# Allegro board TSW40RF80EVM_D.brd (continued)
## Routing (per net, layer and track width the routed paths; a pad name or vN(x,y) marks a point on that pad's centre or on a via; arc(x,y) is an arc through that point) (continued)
DVDD_1P0V: length 120.4
  L8_SIG w0.102: 18.08,19.7 18.08,20.12 17.88,20.32 17.88,22.1 v1(18.25,22.47)
  L8_SIG w0.127: v1(91.47,13.44) 90.93,13.97 89.18,13.97 88.04,12.83 87.73,12.83 87.86,12.7 87.86,12.34 87.58,12.06 87.22,12.06 86.94,12.34 86.94,12.7 87.07,12.83 86.46,12.83 81.05,7.42 74.55,7.42 71.58,10.39 49.35,10.39 47.8,8.84 32.51,8.84 29.84,11.51 21.67,11.51 17.37,15.8 17.37,16.84 18.08,17.55 18.08,19.7
  BOTTOM w0.305: 20.22,22.84 19.57,23.48 ; 19.57,23.48 19.57,23.61 19.76,23.8 ; 19.57,23.48 19.44,23.48 19.23,23.27 ; 21.04,24.49 v1(20.65,24.87) ; 21.04,24.49 21.04,24.46 v1(20.65,24.07) ; 21.04,24.49 C38.1 21.13,24.31 ; v1(19.05,23.27) 18.93,23.27 18.77,23.11 18.77,23.1 18.53,22.86 18.52,22.86 18.25,22.6 v1(18.25,22.47) ; 21.13,24.31 C39.1 ; 21.13,24.31 21.13,24.13 ; v1(20.65,23.27) v1(19.85,24.07) v1(19.85,23.27) ; 21.13,24.13 21.45,23.8 v1(21.45,23.27) ; 21.13,24.13 20.65,23.65 ; C39.1 21.56,23.38 v1(21.45,23.27) ; C39.1 21.29,23.88 21.07,23.66 ; v1(21.45,23.27) 21.56,23.16 21.56,22.78 ; 21.07,23.66 21.07,23.27 21.56,22.78 ; 21.07,23.66 20.68,23.27 ; 19.62,23.03 19.85,23.26 ; 19.62,23.03 19.37,23.27 ; 19.62,23.03 19.85,22.79 ; 21.56,22.78 C41.1
  BOTTOM w0.381: v1(20.65,24.87) v1(19.85,24.87) ; v1(20.65,24.87) v1(20.65,24.07) ; v1(20.65,24.87) v1(19.85,24.07) ; v1(19.85,24.87) v1(20.65,24.07) ; v1(19.85,24.87) v1(19.85,24.07) ; v1(20.65,24.07) v1(19.85,23.27) ; v1(20.65,24.07) v1(21.45,23.27) v1(20.65,23.27) ; v1(20.65,24.07) v1(19.85,24.07) ; v1(20.65,24.07) v1(20.65,23.27) ; v1(20.65,24.07) v1(20.65,23.27) ; v1(19.85,20.07) v1(19.85,20.87) v1(19.85,21.67) v1(19.85,22.47) ; v1(20.65,23.27) v1(19.85,22.47) ; v1(20.65,23.27) v1(19.85,23.27) ; 19.76,23.8 19.76,23.37 v1(19.85,23.27) ; v1(19.85,23.27) v1(19.85,22.47) ; v1(19.85,23.27) v1(19.05,23.27)
  vias: v1(28.65,18.03) v1(28.65,16.99) v1(29.54,18.03) v1(29.54,16.99) v1(30.4,18.03) v1(30.4,16.99) v1(31.27,18.03) v1(31.27,16.99) v1(32.16,18.03) v1(32.16,16.99) v1(33.02,18) v1(33.02,16.97)
GND: length 4342
  TOP w0.127: D1.2 v1(76.4,50.5)
  TOP w0.203: v3(31.14,56.3) 30.11,56.3 v3(29.67,56.74) ; v3(21.26,57.63) 21.46,57.43 21.67,57.43 ; v3(31.14,59.3) 29.83,59.3 29.36,59.77 ; v3(27.3,58.83) 27.3,58.67 27.43,58.55 U4.2 ; v3(31.14,57.8) 29.91,57.8 29.39,57.28 ; v3(24.94,56.82) 24.69,57.07 24.69,57.12 ; v1(152.5,46.48) 148.84,46.48 148.08,47.24 ; v3(31.14,60.8) 30.11,60.8 v3(29.64,60.33) ; v3(21.11,60.12) 21.44,59.79 21.56,59.79 ; U3.2 v8(27.41,61.29) ; 24.69,58.04 24.69,58.06 v8(24.23,58.52) ; v3(40.94,63.47) 40.94,63.45 ; U29.2 v3(22.1,61.14) ; 24.66,59.66 v8(24.66,59.21)
  TOP w0.254: 135.05,18.59 J15.MT1 ; 26.92,57.84 26.64,57.84 v8(26.44,57.63) ; v3(31.67,63.68) 31.79,63.56 U2.18
  TOP w0.305: v3(40.94,60.3) 42.31,60.3 v3(42.34,60.33) 42.77,60.33 v3(43.18,60.73) 43.87,61.42 v3(44.07,61.42) 44.09,61.44 v3(45.03,61.44) ; C186.1 70.89,49.26 v5(70.83,49.2) 71.07,48.97 C191.1 ; v5(37.23,44.56) 37.06,44.6 36.38,44.6 v5(36.21,44.56) ; U21.18 65.52,11.39 v1(65.53,11.4) ; v1(101.88,49.56) 101.88,49.55 C250.1 ; v3(40.97,53.54) 41.2,53.77 42.14,53.77 v3(42.34,53.57) 43.46,53.57 v3(43.61,53.72) 43.89,53.72 v3(44.37,54.2) 44.96,54.79 v3(45.03,54.79) ; v1(15.05,20.87) v1(14.25,20.87) 14.24,20.87 v1(13.03,19.66) ; C264.2 88.15,41.99 v1(88.22,42.07) ; C236.1 34.18,44.47 v5(34.18,44.56) ; v1(14.81,17.14) 14.81,18.16 v1(15.06,18.41) ; 39.65,38.13 39.47,38.13 v5(39.26,38.08) ; v1(15.05,21.67) v1(14.25,21.67) ; C195.2 72.8,48.49 v3(72.72,48.41) ; v1(40.82,36.86) 40.26,36.86 39.45,37.67 C238.1 ; v5(33.17,39.1) 32.64,39.62 R122.1 ; v5(33.17,42.65) 32.92,42.41 C232.1 ; 114.24,10.87 U23.6 U23.5 114.89,10.94 v6(114.67,10.72) ; v3(39.62,64.85) 39.29,64.52 v3(39.29,63.6) ; v1(48.92,39.73) 48.95,39.7 D5.2 ; v3(39.09,50.57) 38.84,50.32 38.15,50.32 38.07,50.39 ; U2.37 31.79,53.43 v3(31.62,53.26) ; v5(39.26,41) 39.43,41.17 R87.2 ; v3(42.39,61.8) 42.39,62.2 v3(42.9,62.71) 43.26,63.07 v3(44.02,63.07) v3(44.91,63.07) ; v3(44.88,58.19) 44.15,57.45 v3(44.12,57.45) 43.48,56.82 v3(43.26,56.82) 43.23,56.79 v3(42.42,56.79) 42.42,56.8 v3(40.94,56.8) ; v3(42.42,55.27) v3(43.46,55.27) 43.66,55.27 v3(44.27,55.88) 44.88,56.49 v3(45.06,56.49) ; C241.2 32.87,43.41 v5(33.17,43.57) ; v3(39.98,51.92) 39.29,52.6 v3(39.29,53.65) ; v1(86.5,42.07) 86.57,41.99 C265.1 ; v5(70.83,47.17) 71.07,47.4 C188.1 71.07,47.95 v5(70.83,48.18) ; U17.9 93.38,16 U17.6 ; U21.8 v5(65.52,7.87) v5(65.52,8.57) ; v1(152.5,42.67) 152.53,42.67 v2(153.16,42.04) ; v6(93.34,16.42) 93.12,16.65 U17.5 ; v5(39.26,43.54) 39.36,43.64 C234.1 ; D3.2 49.12,35.38 v1(49.12,34.62) ; v5(38.25,38.08) 37.95,38.08 37.95,37.97 ; v3(45.03,59.79) 44.42,59.79 v3(44.04,59.41) 43.23,58.6 v3(43.18,58.6) 42.57,58.6 v3(42.39,58.78) ; v5(69.82,49.2) 70.13,49.51 C182.2
  TOP w0.381: C340.2 113.94,37.54 v1(113.94,38.25) ; v1(30.56,21.34) v1(28.91,21.34) 26.85,21.34 26.8,21.29 v1(24.38,21.29) 23.83,21.29 ; R190.1 110.44,41.15 v2(110.29,41) ; v1(22.25,22.47) U1.C2 v1(22.25,20.87) ; R189.1 111.43,41.12 v2(111.3,41) 111.43,40.87 R188.1 111.43,40.11 v2(111.3,39.98) 111.05,39.73 C348.2 111.05,39.22 v2(111.3,38.96) ; v1(22.63,31.14) 22.66,31.11 v1(25.93,31.11) 25.96,31.09 v1(28.22,31.09) v1(29.79,31.09) 30.58,31.09 ; 39.24,38.3 39.45,38.1 C238.1
  TOP w0.432: JP4.3 67.7,34.64 ; JP4.3 66.05,33 ; JP4.3 65.79,33.82 ; JP4.3 67.97,33.82 ; JP4.3 66.05,34.64 ; JP4.3 67.7,33 ; JP4.3 66.88,32.73 ; TP7.1 88.27,19 ; TP7.1 87.35,16.87 ; TP7.1 87.05,17.78 ; TP7.1 89.18,18.69 ; TP7.1 88.27,16.56 ; TP7.1 89.18,16.87 ; TP7.1 87.35,18.69 ; TP7.1 89.48,17.78 ; 119.51,44.91 TP9.1 ; TP9.1 121.33,46.73 ; TP9.1 121.33,44.91 ; TP9.1 119.51,46.73 ; TP9.1 120.42,47.04 ; TP9.1 120.42,44.6 ; J17.2 139.94,2.75 ; J17.2 137.05,2.75 ; J17.2 138.49,7.62 ; J17.2 138.49,2.75 ; J17.2 137.05,5.19 ; J17.2 139.94,7.62 ; J17.2 139.94,5.19 ; TP14.1 77.29,44.86 ; TP14.1 76.07,46.08 ; TP14.1 75.16,43.94 ; TP14.1 76.07,43.64 ; TP14.1 76.99,45.77 ; TP14.1 75.16,45.77 ; TP14.1 76.99,43.94 ; TP14.1 74.85,44.86 ; J15.5 130.84,19.08 ; J15.5 130.01,18.81 ; J15.5 130.01,17.16 ; J15.5 130.84,16.89 ; J15.5 131.66,17.16 ; J15.5 131.66,18.81 ; J38.2 113.37,32.45 ; J38.2 112.5,32.16 ; J38.2 111.33,33.32 ; J38.2 111.62,34.2 ; J38.2 111.62,32.45 ; J38.2 113.67,33.32 ; J38.2 112.5,34.49 ; J38.2 113.37,34.2 ; TP8.1 45.06,48.82 ; TP8.1 45.06,50.65 ; TP8.1 42.93,49.73 ; TP8.1 45.36,49.73 ; TP8.1 44.15,48.51 ; TP8.1 43.23,50.65 ; TP8.1 43.23,48.82 ; 80.56,9.75 JP2.3 ; JP2.3 81.38,9.49 ; JP2.3 82.21,9.75 ; JP2.3 80.29,10.58 ; JP2.3 82.47,10.58 ; JP2.3 80.56,11.4 ; JP2.3 82.21,11.4 ; 150.81,3.54 TP11.1 ; TP11.1 153.59,2.36 ; TP11.1 150.81,1.18 ; TP11.1 153.18,1.18 ; TP11.1 150.39,2.36 ; TP11.1 151.99,3.96 ; TP11.1 151.99,0.76 ; TP11.1 153.18,3.54 ; 20.27,46.38 TP6.1 ; TP6.1 21.18,46.69 ; TP6.1 19.36,48.51 ; TP6.1 19.36,46.69 ; TP6.1 21.49,47.6 ; TP6.1 21.18,48.51 ; TP6.1 19.05,47.6 ; TP6.1 20.27,48.82 ; 150.44,65.74 TP1.1 ; TP1.1 152.58,66.65 ; TP1.1 150.75,64.82 ; TP1.1 152.88,65.74 ; TP1.1 152.58,64.82 ; TP1.1 150.75,66.65 ; TP1.1 151.66,64.52 ; TP1.1 151.66,66.95 ; 13.58,42.67 HS1.MTG1 ; HS1.MTG1 16.87,45.96 ; HS1.MTG1 16.87,39.38 ; HS1.MTG1 20.16,42.67 ; HS1.MTG1 14.49,40.3 ; HS1.MTG1 19.24,40.3 ; HS1.MTG1 19.24,45.05 ; HS1.MTG1 14.49,45.05 ; 78.59,9.49 JP1.3 ; JP1.3 79.41,9.75 ; JP1.3 77.76,9.75 ; JP1.3 79.41,11.4 ; JP1.3 77.49,10.58 ; JP1.3 77.76,11.4 ; JP1.3 79.68,10.58 ; 5.61,8.89 TP2.1 ; TP2.1 7.44,8.89 ; TP2.1 7.44,10.72 ; TP2.1 6.53,11.02 ; TP2.1 5.61,10.72 ; TP2.1 6.53,8.58 ; TP2.1 5.31,9.8 ; TP2.1 7.75,9.8 ; J12.4 60.79,44.75 ; J12.4 57.9,45.97 ; J12.4 59.56,47.64 ; J12.4 58.34,47.2 ; J12.4 61.23,45.97 ; J12.4 60.79,47.2 ; J12.4 58.34,44.75 ; J12.4 59.56,44.31 ; 81.85,36.28 JP8.2 ; JP8.2 81.58,35.46 ; JP8.2 83.5,34.63 ; JP8.2 83.77,35.46 ; JP8.2 83.5,36.28 ; JP8.2 81.85,34.63 ; 52.82,51.05 J12.2 ; J12.2 54.48,49.39 ; J12.2 56.15,51.05 ; J12.2 53.26,49.83 ; J12.2 55.71,49.83 ; 18.93,6.95 HS1.MTG2 ; HS1.MTG2 23.69,2.2 ; HS1.MTG2 23.69,6.95 ; HS1.MTG2 18.02,4.57 ; HS1.MTG2 21.31,7.86 ; HS1.MTG2 21.31,1.28 ; HS1.MTG2 24.6,4.57 ; HS1.MTG2 18.93,2.2 ; 78.73,48.4 JP3.2 ; JP3.2 80.65,49.23 ; JP3.2 80.38,48.4 ; JP3.2 80.38,50.05 ; JP3.2 78.73,50.05 ; JP3.2 78.46,49.23 ; 136.08,14.26 J15.MT1 ; J15.MT1 136.08,19.11 ; J15.MT1 137.34,16.69 ; J15.MT1 134.82,16.69 ; J15.MT1 134.82,14.26 ; J15.MT1 137.34,14.26 ; 128.79,14.26 J15.MT2 ; J15.MT2 130.05,19.11 ; J15.MT2 128.79,19.11 ; J15.MT2 127.53,19.11 ; J15.MT2 130.05,16.69 ; J12.5 56.15,45.97 ; J12.5 54.48,44.31 ; J12.5 55.71,44.75 ; J12.5 52.82,45.97 ; J12.5 53.26,44.75 ; J12.5 54.48,47.64 ; J12.5 55.71,47.2 ; J12.5 53.26,47.2 ; JP7.2 81.87,43.19 ; JP7.2 79.96,42.37 ; JP7.2 82.14,42.37 ; JP7.2 80.23,43.19 ; 134.35,10.22 J17.3 ; J17.3 135.79,10.22 ; J17.3 134.35,7.79 ; J17.3 135.79,5.35 ; J17.3 137.24,7.79 ; J17.3 137.24,10.22 ; J12.3 61.23,51.05 ; J12.3 60.79,49.83 ; J12.3 59.56,52.72 ; J12.3 60.79,52.28 ; J12.3 57.9,51.05 ; J12.3 58.34,52.28 ; 66.44,41.1 JP5.1 ; JP5.1 66.44,42.19 ; JP5.1 68.62,42.19 ; JP5.1 67.53,42.19
  TOP w0.508: C235.1 34.11,44.63 v5(34.18,44.56) ; C236.1 34.36,44.56 v5(35.2,44.56) v5(36.21,44.56) v5(37.23,44.56) v5(38.25,44.56) ; C342.1 111.15,38.81 v2(111.3,38.96) ; C425.2 115.39,10.08 v6(114.67,10.08) v6(113.92,10.08) ; R343.2 113.96,38.27 v1(113.94,38.25) ; R200.2 117.2,41.1 117.42,40.87 117.42,40.49 ; U23.9 114.24,10.71 114.24,10.87 114.94,11.56 C426.1 ; C80.1 v1(27.56,12.7) ; 132.26,40.77 131.85,41.17 131.44,41.17 ; R206.2 124.36,41.22 124.79,40.79
  L2_GND w0.406: MT3.1 95.36,32.91 ; MT3.1 92.4,35.87 ; MT3.1 93.88,32.37 ; MT3.1 93.88,36.41 ; MT3.1 95.36,35.87 ; MT3.1 91.86,34.39 ; MT3.1 95.9,34.39 ; MT3.1 92.4,32.91
  L2_GND w0.432: J15.MT1 137.34,16.69 ; J15.MT1 137.34,19.11 ; J15.MT1 136.08,14.26 ; J15.MT1 134.82,16.69 ; J15.MT1 137.34,14.26 ; J15.MT1 134.82,14.26 ; J15.MT1 136.08,19.11 ; J12.4 59.56,47.64 ; J12.4 61.23,45.97 ; J12.4 60.79,44.75 ; J12.4 58.34,47.2 ; J12.4 57.9,45.97 ; J12.4 60.79,47.2 ; J12.4 59.56,44.31 ; J12.4 58.34,44.75 ; 18.93,6.95 HS1.MTG2 ; HS1.MTG2 23.69,6.95 ; HS1.MTG2 23.69,2.2 ; HS1.MTG2 18.02,4.57 ; HS1.MTG2 18.93,2.2 ; HS1.MTG2 21.31,7.86 ; HS1.MTG2 24.6,4.57 ; HS1.MTG2 21.31,1.28 ; 111.62,32.45 J38.2 ; J38.2 112.5,34.49 ; J38.2 113.67,33.32 ; J38.2 113.37,32.45 ; J38.2 113.37,34.2 ; J38.2 112.5,32.16 ; J38.2 111.33,33.32 ; J38.2 111.62,34.2 ; 81.85,34.63 JP8.2 ; JP8.2 83.5,34.63 ; JP8.2 81.58,35.46 ; JP8.2 83.77,35.46 ; JP8.2 83.5,36.28 ; JP8.2 81.85,36.28 ; TP9.1 121.33,44.91 ; TP9.1 119.51,46.73 ; TP9.1 119.2,45.82 ; TP9.1 120.42,44.6 ; TP9.1 119.51,44.91 ; TP9.1 120.42,47.04 ; TP9.1 121.64,45.82 ; TP9.1 121.33,46.73 ; 67.53,40 JP5.1 ; JP5.1 66.71,41.92 ; JP5.1 66.71,40.27 ; JP5.1 67.53,42.19 ; JP5.1 68.35,41.92 ; JP5.1 68.35,40.27 ; JP5.1 66.44,41.1 ; JP3.2 80.38,50.05 ; JP3.2 80.38,48.4 ; JP3.2 78.73,50.05 ; JP3.2 80.65,49.23 ; JP3.2 78.73,48.4 ; JP3.2 78.46,49.23 ; J15.5 131.66,17.16 ; J15.5 130.01,18.81 ; J15.5 130.01,17.16 ; J15.5 130.84,19.08 ; J15.5 131.66,18.81 ; J15.5 130.84,16.89 ; 77.76,9.75 JP1.3 ; JP1.3 79.68,10.58 ; JP1.3 77.49,10.58 ; JP1.3 79.41,9.75 ; JP1.3 77.76,11.4 ; JP1.3 79.41,11.4 ; JP1.3 78.59,9.49 ; 7.72,63.51 MT2.1 ; MT2.1 5.7,65.53 ; MT2.1 9.74,65.53 ; MT2.1 6.24,67.01 ; MT2.1 6.24,64.05 ; MT2.1 9.2,67.01 ; MT2.1 9.2,64.05 ; MT2.1 7.72,67.55 ; 5.31,9.8 TP2.1 ; TP2.1 6.53,8.58 ; TP2.1 5.61,8.89 ; TP2.1 7.44,10.72 ; TP2.1 7.44,8.89 ; TP2.1 6.53,11.02 ; TP2.1 5.61,10.72 ; TP2.1 7.75,9.8 ; J12.2 56.15,51.05 ; J12.2 55.71,49.83 ; J12.2 53.26,52.28 ; J12.2 52.82,51.05 ; J12.2 54.48,49.39 ; J12.2 54.48,52.72 ; J12.2 53.26,49.83 ; J12.2 55.71,52.28 ; J17.3 137.24,7.79 ; J17.3 135.79,5.35 ; J17.3 134.35,7.79 ; J17.3 137.24,10.22 ; J17.3 135.79,10.22 ; J17.3 134.35,5.35 ; J17.3 134.35,10.22 ; 7.98,12.71 MT1.1 ; MT1.1 9.45,16.21 ; MT1.1 6.5,16.21 ; MT1.1 10,14.73 ; MT1.1 7.98,16.75 ; MT1.1 6.5,13.25 ; MT1.1 9.45,13.25 ; MT1.1 5.96,14.73 ; TP1.1 152.88,65.74 ; TP1.1 150.75,64.82 ; TP1.1 150.44,65.74 ; TP1.1 152.58,66.65 ; TP1.1 150.75,66.65 ; TP1.1 151.66,64.52 ; TP1.1 152.58,64.82 ; TP1.1 151.66,66.95 ; JP4.3 67.97,33.82 ; JP4.3 66.05,34.64 ; JP4.3 66.05,33 ; JP4.3 66.88,32.73 ; JP4.3 65.79,33.82 ; JP4.3 67.7,34.64 ; JP4.3 67.7,33 ; TP14.1 76.07,46.08 ; TP14.1 75.16,43.94 ; TP14.1 74.85,44.86 ; TP14.1 77.29,44.86 ; TP14.1 76.99,43.94 ; TP14.1 75.16,45.77 ; TP14.1 76.07,43.64 ; TP14.1 76.99,45.77 ; 43.23,48.82 TP8.1 ; TP8.1 45.06,50.65 ; TP8.1 42.93,49.73 ; TP8.1 45.36,49.73 ; TP8.1 43.23,50.65 ; TP8.1 44.15,48.51 ; TP8.1 45.06,48.82 ; TP8.1 44.15,50.95 ; J12.3 60.79,52.28 ; J12.3 59.56,52.72 ; J12.3 60.79,49.83 ; J12.3 57.9,51.05 ; J12.3 61.23,51.05 ; J12.3 58.34,52.28 ; J12.3 58.34,49.83 ; J15.MT2 130.05,19.11 ; J15.MT2 130.05,16.69 ; J15.MT2 127.53,14.26 ; J15.MT2 128.79,14.26 ; J15.MT2 128.79,19.11 ; J15.MT2 127.53,16.69 ; J15.MT2 127.53,19.11 ; 80.29,10.58 JP2.3 ; JP2.3 80.56,9.75 ; JP2.3 82.21,11.4 ; JP2.3 82.21,9.75 ; JP2.3 82.47,10.58 ; JP2.3 81.38,9.49 ; JP2.3 80.56,11.4 ; TP6.1 21.18,46.69 ; TP6.1 19.36,48.51 ; TP6.1 19.36,46.69 ; TP6.1 20.27,46.38 ; TP6.1 21.49,47.6 ; TP6.1 20.27,48.82 ; TP6.1 19.05,47.6 ; TP6.1 21.18,48.51 ; JP7.2 82.14,42.37 ; JP7.2 81.87,43.19 ; JP7.2 79.96,42.37 ; JP7.2 80.23,41.54 ; JP7.2 80.23,43.19 ; JP7.2 81.87,41.54 ; 14.49,45.05 HS1.MTG1 ; HS1.MTG1 19.24,45.05 ; HS1.MTG1 20.16,42.67 ; HS1.MTG1 16.87,45.96 ; HS1.MTG1 19.24,40.3 ; HS1.MTG1 16.87,39.38 ; HS1.MTG1 13.58,42.67 ; HS1.MTG1 14.49,40.3 ; J17.2 139.94,5.19 ; J17.2 137.05,5.19 ; J17.2 139.94,7.62 ; J17.2 138.49,2.75 ; J17.2 137.05,2.75 ; J17.2 138.49,7.62 ; J17.2 139.94,2.75 ; 88.27,16.56 TP7.1 ; TP7.1 87.35,16.87 ; TP7.1 89.18,16.87 ; TP7.1 87.35,18.69 ; TP7.1 87.05,17.78 ; TP7.1 88.27,19 ; TP7.1 89.48,17.78 ; TP7.1 89.18,18.69 ; 150.81,1.18 TP11.1 ; TP11.1 151.99,0.76 ; TP11.1 153.18,3.54 ; TP11.1 153.59,2.36 ; TP11.1 153.18,1.18 ; TP11.1 150.39,2.36 ; TP11.1 150.81,3.54 ; TP11.1 151.99,3.96 ; 53.26,47.2 J12.5 ; J12.5 54.48,47.64 ; J12.5 54.48,44.31 ; J12.5 55.71,44.75 ; J12.5 52.82,45.97 ; J12.5 56.15,45.97 ; J12.5 53.26,44.75 ; J12.5 55.71,47.2
  L3_PWR_SIG w0.432: 6.5,16.21 MT1.1 ; MT1.1 6.5,13.25 ; MT1.1 7.98,16.75 ; MT1.1 9.45,13.25 ; MT1.1 5.96,14.73 ; MT1.1 7.98,12.71 ; TP6.1 20.27,48.82 ; TP6.1 20.27,46.38 ; TP6.1 21.49,47.6 ; TP6.1 21.18,48.51 ; TP6.1 21.18,46.69 ; TP6.1 19.36,48.51 ; TP6.1 19.36,46.69 ; TP6.1 19.05,47.6 ; 79.09,48.16 JP3.2 ; JP3.2 78.73,50.05 ; JP3.2 78.46,49.23 ; JP3.2 78.73,48.4 ; J15.MT1 136.08,19.11 ; J15.MT1 136.08,14.26 ; J15.MT1 137.34,14.26 ; J15.MT1 134.82,14.26 ; J15.MT1 134.82,16.69 ; J15.MT1 137.34,19.11 ; J15.MT1 137.34,16.69 ; HS1.MTG1 19.24,45.05 ; HS1.MTG1 14.49,45.05 ; HS1.MTG1 13.58,42.67 ; HS1.MTG1 20.16,42.67 ; HS1.MTG1 16.87,45.96 ; HS1.MTG1 19.24,40.3 ; HS1.MTG1 16.87,39.38 ; HS1.MTG1 14.49,40.3 ; TP9.1 120.42,47.04 ; TP9.1 121.33,46.73 ; TP9.1 121.33,44.91 ; TP9.1 121.64,45.82 ; TP9.1 119.51,46.73 ; TP9.1 119.2,45.82 ; 18.02,4.57 HS1.MTG2 ; HS1.MTG2 23.69,2.2 ; HS1.MTG2 24.6,4.57 ; HS1.MTG2 21.31,1.28 ; HS1.MTG2 18.93,6.95 ; HS1.MTG2 18.93,2.2 ; HS1.MTG2 23.69,6.95 ; 58.34,44.75 J12.4 ; J12.4 57.9,45.97 ; J12.4 60.79,44.75 ; J12.4 59.56,44.31 ; J12.4 60.79,47.2 ; J12.4 59.56,47.64 ; J12.4 58.34,47.2 ; J12.4 61.23,45.97 ; TP7.1 89.18,18.69 ; TP7.1 88.27,16.56 ; TP7.1 88.27,19 ; TP7.1 87.35,18.69 ; TP7.1 87.35,16.87 ; TP7.1 89.48,17.78 ; TP7.1 89.18,16.87 ; TP7.1 87.05,17.78 ; 66.05,33 JP4.3 ; JP4.3 67.7,34.64 ; JP4.3 66.88,32.73 ; JP4.3 67.97,33.82 ; JP4.3 67.7,33 ; JP4.3 66.05,34.64 ; JP4.3 65.79,33.82 ; J17.2 139.94,5.19 ; J17.2 138.49,7.62 ; J17.2 139.94,7.62 ; J17.2 137.05,5.19 ; J17.2 139.94,2.75 ; J17.2 138.49,2.75 ; J17.2 137.05,2.75 ; 43.23,50.65 TP8.1 ; TP8.1 43.23,48.82 ; TP8.1 44.15,48.51 ; TP8.1 42.93,49.73 ; TP8.1 45.36,49.73 ; TP8.1 45.06,50.65 ; TP8.1 44.15,50.95 ; TP8.1 45.06,48.82 ; 127.53,16.69 J15.MT2 ; J15.MT2 128.79,14.26 ; J15.MT2 130.05,16.69 ; J15.MT2 127.53,14.26 ; MT2.1 9.2,64.05 ; MT2.1 7.72,63.51 ; MT2.1 9.74,65.53 ; MT2.1 6.24,67.01 ; MT2.1 9.2,67.01 ; MT2.1 7.72,67.55 ; MT2.1 6.24,64.05 ; MT2.1 5.7,65.53 ; TP14.1 76.99,45.77 ; TP14.1 75.16,43.94 ; TP14.1 75.16,45.77 ; TP14.1 76.07,46.08 ; TP14.1 74.85,44.86 ; TP14.1 77.29,44.86 ; TP14.1 76.07,43.64 ; TP14.1 76.99,43.94 ; 77.76,11.4 JP1.3 ; JP1.3 77.49,10.58 ; JP1.3 79.41,11.4 ; JP1.3 79.68,10.58 ; TP11.1 153.59,2.36 ; TP11.1 151.99,0.76 ; TP11.1 150.81,3.54 ; TP11.1 150.39,2.36 ; TP11.1 150.81,1.18 ; TP11.1 153.18,3.54 ; TP11.1 151.99,3.96 ; TP11.1 153.18,1.18 ; 53.26,47.2 J12.5 ; J12.5 54.48,44.31 ; J12.5 55.71,44.75 ; J12.5 56.15,45.97 ; J12.5 52.82,45.97 ; J12.5 55.71,47.2 ; J12.5 54.48,47.64 ; J12.5 53.26,44.75 ; 150.44,65.74 TP1.1 ; TP1.1 150.75,66.65 ; TP1.1 150.75,64.82 ; TP1.1 152.58,66.65 ; TP1.1 152.88,65.74 ; TP1.1 151.66,64.52 ; TP1.1 152.58,64.82 ; TP1.1 151.66,66.95 ; JP2.3 82.21,11.4 ; JP2.3 82.47,10.58 ; JP2.3 80.56,11.4 ; JP2.3 80.29,10.58 ; J12.3 59.56,52.72 ; J12.3 58.34,49.83 ; J12.3 58.34,52.28 ; J12.3 60.79,52.28 ; J12.3 61.23,51.05 ; J12.3 57.9,51.05 ; J12.3 60.79,49.83 ; J12.2 55.71,52.28 ; J12.2 56.15,51.05 ; J12.2 54.48,49.39 ; J12.2 52.82,51.05 ; J12.2 53.26,52.28 ; J12.2 55.71,49.83 ; J12.2 53.26,49.83 ; J12.2 54.48,52.72 ; 5.31,9.8 TP2.1 ; TP2.1 5.61,8.89 ; TP2.1 7.44,10.72 ; TP2.1 6.53,11.02 ; TP2.1 7.75,9.8 ; TP2.1 6.53,8.58 ; TP2.1 7.44,8.89 ; TP2.1 5.61,10.72 ; 135.79,5.35 J17.3 ; J17.3 135.79,10.22 ; J17.3 137.24,10.22 ; J17.3 134.35,5.35 ; J17.3 134.35,7.79 ; J17.3 137.24,7.79 ; J17.3 134.35,10.22 ; 130.38,16.91 J15.5 ; J15.5 130.01,17.16 ; J15.5 131.66,17.16 ; J15.5 130.84,16.89 ; JP5.1 67.53,42.19 ; JP5.1 66.71,41.92 ; JP5.1 66.71,40.27 ; JP5.1 66.44,41.1 ; JP5.1 68.35,41.92 ; JP5.1 68.35,40.27 ; JP5.1 67.53,40 ; 81.85,34.63 JP8.2 ; JP8.2 82.22,34.39 ; JP8.2 81.58,35.46 ; JP8.2 81.61,35
  L4_SIG w0.406: 91.86,34.39 MT3.1 ; MT3.1 93.88,36.41 ; MT3.1 95.36,32.91 ; MT3.1 92.4,32.91 ; MT3.1 93.88,32.37 ; MT3.1 95.36,35.87 ; MT3.1 95.9,34.39 ; MT3.1 92.4,35.87
  L4_SIG w0.432: 14.49,45.05 HS1.MTG1 ; HS1.MTG1 20.16,42.67 ; HS1.MTG1 19.24,40.3 ; HS1.MTG1 16.87,39.38 ; HS1.MTG1 19.24,45.05 ; HS1.MTG1 14.49,40.3 ; HS1.MTG1 13.58,42.67 ; HS1.MTG1 16.87,45.96 ; 58.34,52.28 J12.3 ; J12.3 60.79,52.28 ; J12.3 59.56,52.72 ; J12.3 57.9,51.05 ; J12.3 61.23,51.05 ; J12.3 60.79,49.83 ; J12.3 58.34,49.83 ; 135.79,5.35 J17.3 ; J17.3 137.24,10.22 ; J17.3 135.79,10.22 ; J17.3 137.24,7.79 ; J17.3 134.35,10.22 ; J17.3 134.35,5.35 ; J17.3 134.35,7.79 ; JP8.2 83.5,34.63 ; JP8.2 83.5,36.28 ; JP8.2 81.58,35.46 ; JP8.2 81.85,34.63 ; JP8.2 81.85,36.28 ; JP8.2 83.77,35.46 ; JP2.3 82.21,9.75 ; JP2.3 82.47,10.58 ; JP2.3 80.56,9.75 ; JP2.3 82.21,11.4 ; JP2.3 81.38,9.49 ; JP2.3 80.56,11.4 ; JP2.3 80.29,10.58 ; JP3.2 80.65,49.23 ; JP3.2 80.38,50.05 ; JP3.2 78.73,50.05 ; JP3.2 78.73,48.4 ; JP3.2 78.46,49.23 ; JP3.2 80.38,48.4 ; 150.75,64.82 TP1.1 ; TP1.1 152.58,66.65 ; TP1.1 150.75,66.65 ; TP1.1 150.44,65.74 ; TP1.1 151.66,66.95 ; TP1.1 152.88,65.74 ; TP1.1 152.58,64.82 ; TP1.1 151.66,64.52 ; J12.4 61.23,45.97 ; J12.4 60.79,44.75 ; J12.4 60.79,47.2 ; J12.4 59.56,47.64 ; J12.4 58.34,44.75 ; J12.4 59.56,44.31 ; J12.4 58.34,47.2 ; J12.4 57.9,45.97 ; TP11.1 153.18,3.54 ; TP11.1 150.81,1.18 ; TP11.1 153.18,1.18 ; TP11.1 151.99,0.76 ; TP11.1 153.59,2.36 ; TP11.1 151.99,3.96 ; TP11.1 150.39,2.36 ; TP11.1 150.81,3.54 ; TP7.1 89.48,17.78 ; TP7.1 89.18,18.69 ; TP7.1 87.35,18.69 ; TP7.1 89.18,16.87 ; TP7.1 88.27,16.56 ; TP7.1 87.05,17.78 ; TP7.1 87.35,16.87 ; TP7.1 88.27,19 ; 79.96,42.37 JP7.2 ; JP7.2 80.23,43.19 ; JP7.2 81.87,43.19 ; JP7.2 81.87,41.54 ; JP7.2 82.14,42.37 ; JP7.2 80.23,41.54 ; 19.05,47.6 TP6.1 ; TP6.1 20.27,48.82 ; TP6.1 19.36,46.69 ; TP6.1 20.27,46.38 ; TP6.1 21.49,47.6 ; TP6.1 19.36,48.51 ; TP6.1 21.18,46.69 ; TP6.1 21.18,48.51 ; 6.24,67.01 MT2.1 ; MT2.1 9.2,64.05 ; MT2.1 9.74,65.53 ; MT2.1 7.72,63.51 ; MT2.1 9.2,67.01 ; MT2.1 7.72,67.55 ; MT2.1 6.24,64.05 ; MT2.1 5.7,65.53 ; 77.49,10.58 JP1.3 ; JP1.3 79.41,11.4 ; JP1.3 79.68,10.58 ; JP1.3 78.59,9.49 ; JP1.3 79.41,9.75 ; JP1.3 77.76,11.4 ; JP1.3 77.76,9.75 ; 134.82,16.69 J15.MT1 ; J15.MT1 137.34,16.69 ; J15.MT1 137.34,14.26 ; J15.MT1 137.34,19.11 ; J15.MT1 134.82,14.26 ; J15.MT1 136.08,19.11 ; J15.MT1 136.08,14.26 ; J12.2 55.71,49.83 ; J12.2 53.26,52.28 ; J12.2 55.71,52.28 ; J12.2 52.82,51.05 ; J12.2 53.26,49.83 ; J12.2 54.48,49.39 ; J12.2 54.48,52.72 ; J12.2 56.15,51.05 ; MT1.1 10,14.73 ; MT1.1 7.98,12.71 ; MT1.1 6.5,16.21 ; MT1.1 5.96,14.73 ; MT1.1 9.45,13.25 ; MT1.1 7.98,16.75 ; MT1.1 6.5,13.25 ; MT1.1 9.45,16.21 ; 54.48,44.31 J12.5 ; J12.5 53.26,44.75 ; J12.5 54.48,47.64 ; J12.5 55.71,44.75 ; J12.5 56.15,45.97 ; J12.5 52.82,45.97 ; J12.5 55.71,47.2 ; J12.5 53.26,47.2 ; TP9.1 120.42,47.04 ; TP9.1 121.33,44.91 ; TP9.1 119.51,44.91 ; TP9.1 121.64,45.82 ; TP9.1 121.33,46.73 ; TP9.1 119.51,46.73 ; TP9.1 119.2,45.82 ; TP9.1 120.42,44.6 ; TP14.1 76.07,46.08 ; TP14.1 75.16,45.77 ; TP14.1 76.58,46.04 ; TP14.1 74.85,44.86 ; J15.MT2 128.79,19.11 ; J15.MT2 130.05,19.11 ; J15.MT2 130.05,16.69 ; J15.MT2 127.53,16.69 ; J15.MT2 128.79,14.26 ; J15.MT2 127.53,19.11 ; J15.MT2 127.53,14.26 ; JP5.1 68.35,40.27 ; JP5.1 66.44,41.1 ; JP5.1 66.71,41.92 ; JP5.1 67.53,40 ; JP5.1 66.71,40.27 ; JP4.3 67.7,34.64 ; JP4.3 66.88,32.73 ; JP4.3 67.97,33.82 ; JP4.3 65.79,33.82 ; JP4.3 66.05,34.64 ; JP4.3 66.05,33 ; JP4.3 67.7,33 ; TP8.1 45.06,50.65 ; TP8.1 43.23,50.65 ; TP8.1 42.93,49.73 ; TP8.1 44.15,50.95 ; TP8.1 45.06,48.82 ; TP8.1 43.23,48.82 ; TP8.1 44.15,48.51 ; 5.61,10.72 TP2.1 ; TP2.1 7.44,8.89 ; TP2.1 6.53,8.58 ; TP2.1 7.44,10.72 ; TP2.1 6.53,11.02 ; TP2.1 5.31,9.8 ; TP2.1 5.61,8.89 ; TP2.1 7.75,9.8 ; 111.33,33.32 J38.2 ; J38.2 112.5,32.16 ; J38.2 111.62,32.45 ; J38.2 111.62,34.2 ; J38.2 113.37,34.2 ; J38.2 113.67,33.32 ; J38.2 113.37,32.45 ; 138.49,2.75 J17.2 ; J17.2 139.94,7.62 ; J17.2 139.94,5.19 ; J17.2 138.49,7.62 ; J17.2 137.05,2.75 ; J17.2 137.05,5.19 ; J17.2 139.94,2.75 ; HS1.MTG2 23.69,2.2 ; HS1.MTG2 18.02,4.57 ; HS1.MTG2 21.31,1.28 ; HS1.MTG2 24.6,4.57 ; HS1.MTG2 18.93,6.95 ; HS1.MTG2 23.69,6.95 ; HS1.MTG2 18.93,2.2 ; HS1.MTG2 21.31,7.86 ; 130.84,16.89 J15.5 ; J15.5 130.01,18.81 ; J15.5 130.84,19.08 ; J15.5 131.66,17.16 ; J15.5 131.66,18.81 ; J15.5 130.01,17.16
  L5_GND w0.406: 92.4,32.91 MT3.1 ; MT3.1 95.36,35.87 ; MT3.1 95.36,32.91 ; MT3.1 92.4,35.87 ; MT3.1 93.88,36.41 ; MT3.1 91.86,34.39 ; MT3.1 95.9,34.39 ; MT3.1 93.88,32.37
  L5_GND w0.432: 52.82,51.05 J12.2 ; J12.2 54.48,49.39 ; J12.2 53.26,49.83 ; J12.2 56.15,51.05 ; J12.2 54.48,52.72 ; J12.2 53.26,52.28 ; J12.2 55.71,49.83 ; J12.2 55.71,52.28 ; 80.23,41.54 JP7.2 ; JP7.2 82.14,42.37 ; JP7.2 80.23,43.19 ; JP7.2 81.87,43.19 ; JP7.2 81.87,41.54 ; JP7.2 79.96,42.37 ; TP14.1 77.29,44.86 ; TP14.1 76.07,46.08 ; TP14.1 74.85,44.86 ; TP14.1 75.16,43.94 ; TP14.1 76.99,43.94 ; TP14.1 76.07,43.64 ; TP14.1 75.16,45.77 ; TP14.1 76.99,45.77 ; 88.27,16.56 TP7.1 ; TP7.1 87.35,18.69 ; TP7.1 89.48,17.78 ; TP7.1 87.35,16.87 ; TP7.1 88.27,19 ; TP7.1 89.18,16.87 ; TP7.1 89.18,18.69 ; TP7.1 87.05,17.78 ; 43.23,48.82 TP8.1 ; TP8.1 43.23,50.65 ; TP8.1 42.93,49.73 ; TP8.1 44.15,48.51 ; TP8.1 45.36,49.73 ; TP8.1 44.15,50.95 ; TP8.1 45.06,48.82 ; TP8.1 45.06,50.65 ; JP5.1 67.53,42.19 ; JP5.1 68.35,40.27 ; JP5.1 66.71,41.92 ; JP5.1 67.53,40 ; JP5.1 66.44,41.1 ; JP5.1 66.71,40.27 ; JP5.1 68.35,41.92 ; 136.08,14.26 J15.MT1 ; J15.MT1 136.08,19.11 ; J15.MT1 137.34,14.26 ; J15.MT1 134.82,14.26 ; J15.MT1 137.34,16.69 ; J15.MT1 134.82,16.69 ; J15.MT1 137.34,19.11 ; 18.93,6.95 HS1.MTG2 ; HS1.MTG2 24.6,4.57 ; HS1.MTG2 18.93,2.2 ; HS1.MTG2 23.69,6.95 ; HS1.MTG2 21.31,1.28 ; HS1.MTG2 18.02,4.57 ; HS1.MTG2 21.31,7.86 ; HS1.MTG2 23.69,2.2 ; 130.01,17.16 J15.5 ; J15.5 130.84,16.89 ; J15.5 130.84,19.08 ; J15.5 131.66,17.16 ; J15.5 131.66,18.81 ; J15.5 130.01,18.81 ; TP11.1 153.18,3.54 ; TP11.1 150.39,2.36 ; TP11.1 151.99,3.96 ; TP11.1 151.99,0.76 ; TP11.1 153.18,1.18 ; TP11.1 150.81,3.54 ; TP11.1 150.81,1.18 ; TP11.1 153.59,2.36 ; TP9.1 120.42,47.04 ; TP9.1 121.64,45.82 ; TP9.1 121.33,46.73 ; TP9.1 119.51,44.91 ; TP9.1 119.2,45.82 ; TP9.1 119.51,46.73 ; TP9.1 120.42,44.6 ; TP9.1 121.33,44.91 ; J12.5 55.71,44.75 ; J12.5 56.15,45.97 ; J12.5 53.26,47.2 ; J12.5 52.82,45.97 ; J12.5 55.71,47.2 ; J12.5 54.48,44.31 ; J12.5 54.48,47.64 ; J12.5 53.26,44.75 ; J12.3 60.79,52.28 ; J12.3 59.56,52.72 ; J12.3 58.34,49.83 ; J12.3 60.79,49.83 ; J12.3 57.9,51.05 ; J12.3 58.34,52.28 ; J12.3 61.23,51.05 ; JP2.3 82.21,9.75 ; JP2.3 80.29,10.58 ; JP2.3 82.21,11.4 ; JP2.3 80.56,9.75 ; JP2.3 82.47,10.58 ; JP2.3 80.56,11.4 ; JP2.3 81.38,9.49 ; 19.05,47.6 TP6.1 ; TP6.1 20.27,46.38 ; TP6.1 19.36,48.51 ; TP6.1 21.18,48.51 ; TP6.1 20.27,48.82 ; TP6.1 21.18,46.69 ; TP6.1 21.49,47.6 ; TP6.1 19.36,46.69 ; MT1.1 10,14.73 ; MT1.1 6.5,16.21 ; MT1.1 5.96,14.73 ; MT1.1 7.98,16.75 ; MT1.1 9.45,13.25 ; MT1.1 9.45,16.21 ; MT1.1 7.98,12.71 ; MT1.1 6.5,13.25 ; 137.05,5.19 J17.2 ; J17.2 138.49,7.62 ; J17.2 139.94,2.75 ; J17.2 138.49,2.75 ; J17.2 139.94,5.19 ; J17.2 137.05,2.75 ; J17.2 139.94,7.62 ; 66.88,32.73 JP4.3 ; JP4.3 67.97,33.82 ; JP4.3 65.79,33.82 ; JP4.3 67.7,34.64 ; JP4.3 66.05,33 ; JP4.3 67.7,33 ; JP4.3 66.05,34.64 ; 6.24,67.01 MT2.1 ; MT2.1 7.72,63.51 ; MT2.1 7.72,67.55 ; MT2.1 9.2,67.01 ; MT2.1 6.24,64.05 ; MT2.1 9.74,65.53 ; MT2.1 5.7,65.53 ; MT2.1 9.2,64.05 ; 5.61,10.72 TP2.1 ; TP2.1 7.44,10.72 ; TP2.1 7.44,8.89 ; TP2.1 6.53,8.58 ; TP2.1 6.53,11.02 ; TP2.1 5.31,9.8 ; TP2.1 5.61,8.89 ; TP2.1 7.75,9.8 ; 127.53,19.11 J15.MT2 ; J15.MT2 130.05,19.11 ; J15.MT2 128.79,19.11 ; J15.MT2 130.05,16.69 ; J15.MT2 128.79,14.26 ; J15.MT2 127.53,14.26 ; J15.MT2 127.53,16.69 ; 150.75,66.65 TP1.1 ; TP1.1 151.66,64.52 ; TP1.1 152.88,65.74 ; TP1.1 150.44,65.74 ; TP1.1 150.75,64.82 ; TP1.1 152.58,66.65 ; TP1.1 151.66,66.95 ; TP1.1 152.58,64.82 ; J38.2 113.67,33.32 ; J38.2 112.5,32.16 ; J38.2 111.62,32.45 ; J38.2 112.5,34.49 ; J38.2 113.37,34.2 ; J38.2 113.37,32.45 ; J38.2 111.33,33.32 ; J38.2 111.62,34.2 ; 81.85,34.63 JP8.2 ; JP8.2 81.58,35.46 ; JP8.2 83.5,36.28 ; JP8.2 83.77,35.46 ; JP8.2 81.85,36.28 ; JP8.2 83.5,34.63 ; HS1.MTG1 19.24,40.3 ; HS1.MTG1 14.49,40.3 ; HS1.MTG1 16.87,39.38 ; HS1.MTG1 13.58,42.67 ; HS1.MTG1 20.16,42.67 ; HS1.MTG1 19.24,45.05 ; HS1.MTG1 16.87,45.96 ; HS1.MTG1 14.49,45.05 ; 78.59,9.49 JP1.3 ; JP1.3 79.68,10.58 ; JP1.3 77.76,9.75 ; JP1.3 77.76,11.4 ; JP1.3 79.41,11.4 ; JP1.3 79.41,9.75 ; JP1.3 77.49,10.58 ; JP3.2 80.65,49.23 ; JP3.2 80.38,48.4 ; JP3.2 78.73,48.4 ; JP3.2 78.73,50.05 ; JP3.2 80.38,50.05 ; JP3.2 78.46,49.23 ; J12.4 60.79,47.2 ; J12.4 59.56,44.31 ; J12.4 60.79,44.75 ; J12.4 59.56,47.64 ; J12.4 61.23,45.97 ; J12.4 58.34,47.2 ; J12.4 57.9,45.97 ; J12.4 58.34,44.75 ; 134.35,5.35 J17.3 ; J17.3 137.24,10.22 ; J17.3 134.35,7.79 ; J17.3 137.24,7.79 ; J17.3 135.79,5.35 ; J17.3 134.35,10.22 ; J17.3 135.79,10.22
  L6_SIG w0.406: MT3.1 95.9,34.39 ; MT3.1 95.36,32.91 ; MT3.1 93.88,32.37 ; MT3.1 93.88,36.41 ; MT3.1 92.4,32.91 ; MT3.1 95.36,35.87 ; MT3.1 91.86,34.39
  L6_SIG w0.432: J12.4 60.79,47.2 ; J12.4 58.34,44.75 ; J12.4 57.9,45.97 ; J12.4 60.79,44.75 ; J12.4 61.23,45.97 ; 130.01,17.16 J15.5 ; J15.5 131.66,18.81 ; J15.5 130.01,18.81 ; J15.5 131.66,17.16 ; J15.5 130.84,16.89 ; J15.5 130.84,19.08 ; 14.49,45.05 HS1.MTG1 ; HS1.MTG1 19.24,45.05 ; HS1.MTG1 20.16,42.67 ; HS1.MTG1 16.87,39.38 ; HS1.MTG1 16.87,45.96 ; HS1.MTG1 13.58,42.67 ; HS1.MTG1 14.49,40.3 ; HS1.MTG1 19.24,40.3 ; JP3.2 80.38,48.4 ; JP3.2 78.73,48.4 ; JP3.2 78.46,49.23 ; JP3.2 80.38,50.05 ; JP3.2 78.73,50.05 ; JP3.2 80.65,49.23 ; 5.61,8.89 TP2.1 ; TP2.1 7.75,9.8 ; TP2.1 6.53,11.02 ; TP2.1 7.44,10.72 ; TP2.1 5.61,10.72 ; TP2.1 5.31,9.8 ; TP2.1 6.53,8.58 ; TP2.1 7.44,8.89 ; 150.75,66.65 TP1.1 ; TP1.1 151.66,66.95 ; TP1.1 152.58,64.82 ; TP1.1 152.58,66.65 ; TP1.1 150.75,64.82 ; TP1.1 152.88,65.74 ; TP1.1 150.44,65.74 ; TP1.1 151.66,64.52 ; J17.2 139.94,2.75 ; J17.2 139.94,7.62 ; J17.2 138.49,2.75 ; J17.2 138.49,7.62 ; J17.2 139.94,5.19 ; J17.2 137.05,5.19 ; J17.2 137.05,2.75 ; J15.MT1 137.34,19.11 ; J15.MT1 137.34,16.69 ; J15.MT1 134.82,14.26 ; J15.MT1 137.34,14.26 ; J15.MT1 136.08,14.26 ; J15.MT1 134.82,16.69 ; J15.MT1 136.08,19.11 ; J38.2 112.5,34.49 ; J38.2 113.67,33.32 ; J38.2 111.33,33.32 ; J38.2 112.5,32.16 ; J38.2 113.37,32.45 ; J38.2 113.37,34.2 ; J38.2 111.62,32.45 ; J38.2 111.62,34.2 ; 127.53,16.69 J15.MT2 ; J15.MT2 127.53,14.26 ; J15.MT2 127.53,19.11 ; J15.MT2 130.05,19.11 ; J15.MT2 128.79,19.11 ; J15.MT2 130.05,16.69 ; J15.MT2 128.79,14.26 ; 87.05,17.78 TP7.1 ; TP7.1 89.18,16.87 ; TP7.1 88.27,16.56 ; TP7.1 88.27,19 ; TP7.1 87.35,18.69 ; TP7.1 87.35,16.87 ; TP7.1 89.18,18.69 ; TP7.1 89.48,17.78 ; TP14.1 76.07,46.08 ; TP14.1 74.85,44.86 ; TP14.1 75.16,43.94 ; TP14.1 76.99,45.77 ; TP14.1 75.16,45.77 ; 18.93,6.95 HS1.MTG2 ; HS1.MTG2 24.6,4.57 ; HS1.MTG2 18.93,2.2 ; HS1.MTG2 21.31,1.28 ; HS1.MTG2 18.02,4.57 ; HS1.MTG2 23.69,6.95 ; HS1.MTG2 21.31,7.86 ; HS1.MTG2 23.69,2.2 ; 134.35,10.22 J17.3 ; J17.3 135.79,10.22 ; J17.3 137.24,10.22 ; J17.3 134.35,5.35 ; J17.3 137.24,7.79 ; J17.3 134.35,7.79 ; J17.3 135.79,5.35 ; MT2.1 9.2,67.01 ; MT2.1 9.2,64.05 ; MT2.1 7.72,63.51 ; MT2.1 9.74,65.53 ; MT2.1 6.24,67.01 ; MT2.1 7.72,67.55 ; MT2.1 5.7,65.53 ; MT2.1 6.24,64.05 ; 44.15,48.51 TP8.1 ; TP8.1 45.36,49.73 ; TP8.1 45.06,50.65 ; TP8.1 42.93,49.73 ; TP8.1 45.06,48.82 ; TP8.1 43.23,48.82 ; 150.81,1.18 TP11.1 ; TP11.1 150.39,2.36 ; TP11.1 151.99,3.96 ; TP11.1 153.59,2.36 ; TP11.1 151.99,0.76 ; TP11.1 153.18,1.18 ; TP11.1 150.81,3.54 ; TP11.1 153.18,3.54 ; J12.2 55.71,49.83 ; J12.2 56.15,51.05 ; J12.2 53.26,49.83 ; J12.2 54.48,49.39 ; J12.2 52.82,51.05 ; J12.5 55.71,44.75 ; J12.5 53.26,47.2 ; J12.5 54.48,47.64 ; J12.5 52.82,45.97 ; J12.5 53.26,44.75 ; J12.5 56.15,45.97 ; JP8.2 83.5,36.28 ; JP8.2 83.77,35.46 ; JP8.2 81.85,36.28 ; JP8.2 81.58,35.46 ; 77.49,10.58 JP1.3 ; JP1.3 77.76,9.75 ; JP1.3 78.59,9.49 ; JP1.3 79.68,10.58 ; JP1.3 79.41,9.75 ; 119.51,46.73 TP9.1 ; TP9.1 119.2,45.82 ; TP9.1 121.33,44.91 ; TP9.1 120.42,47.04 ; TP9.1 121.33,46.73 ; TP9.1 120.42,44.6 ; TP9.1 119.51,44.91 ; TP9.1 121.64,45.82 ; 65.79,33.82 JP4.3 ; JP4.3 66.05,34.64 ; JP4.3 66.88,32.73 ; JP4.3 67.7,33 ; JP4.3 66.05,33 ; JP5.1 68.35,40.27 ; JP5.1 66.71,40.27 ; JP5.1 67.53,40 ; JP5.1 66.71,41.92 ; JP5.1 66.44,41.1 ; 6.5,13.25 MT1.1 ; MT1.1 9.45,13.25 ; MT1.1 6.5,16.21 ; MT1.1 5.96,14.73 ; MT1.1 9.45,16.21 ; MT1.1 10,14.73 ; MT1.1 7.98,16.75 ; MT1.1 7.98,12.71 ; JP2.3 82.21,9.75 ; JP2.3 81.38,9.49 ; JP2.3 82.21,11.4 ; JP2.3 82.47,10.58 ; JP2.3 80.29,10.58 ; JP2.3 80.56,9.75 ; TP6.1 21.18,48.51 ; TP6.1 21.49,47.6 ; TP6.1 20.27,48.82 ; TP6.1 19.36,46.69 ; TP6.1 19.05,47.6 ; TP6.1 19.36,48.51 ; TP6.1 21.18,46.69 ; TP6.1 20.27,46.38 ; J12.3 60.79,49.83 ; J12.3 57.9,51.05 ; J12.3 61.23,51.05 ; J12.3 58.34,49.83
  L7_GND w0.406: 92.4,35.87 MT3.1 ; MT3.1 95.9,34.39 ; MT3.1 93.88,32.37 ; MT3.1 95.36,35.87 ; MT3.1 92.4,32.91 ; MT3.1 93.88,36.41 ; MT3.1 95.36,32.91 ; MT3.1 91.86,34.39
  L7_GND w0.432: J12.2 55.71,49.83 ; J12.2 53.26,49.83 ; J12.2 52.82,51.05 ; J12.2 54.48,49.39 ; J12.2 55.71,52.28 ; J12.2 53.26,52.28 ; J12.2 56.15,51.05 ; J12.2 54.48,52.72 ; 6.53,8.58 TP2.1 ; TP2.1 6.53,11.02 ; TP2.1 7.44,10.72 ; TP2.1 5.31,9.8 ; TP2.1 7.75,9.8 ; TP2.1 5.61,10.72 ; TP2.1 7.44,8.89 ; TP2.1 5.61,8.89 ; J12.3 59.56,52.72 ; J12.3 57.9,51.05 ; J12.3 60.79,49.83 ; J12.3 58.34,49.83 ; J12.3 58.34,52.28 ; J12.3 60.79,52.28 ; J12.3 61.23,51.05 ; 134.35,5.35 J17.3 ; J17.3 135.79,5.35 ; J17.3 137.24,7.79 ; J17.3 137.24,10.22 ; J17.3 134.35,7.79 ; J17.3 134.35,10.22 ; J17.3 135.79,10.22 ; J15.MT2 130.05,16.69 ; J15.MT2 128.79,19.11 ; J15.MT2 130.05,19.11 ; J15.MT2 127.53,19.11 ; J15.MT2 127.53,14.26 ; J15.MT2 127.53,16.69 ; J15.MT2 128.79,14.26 ; HS1.MTG2 24.6,4.57 ; HS1.MTG2 18.93,6.95 ; HS1.MTG2 21.31,7.86 ; HS1.MTG2 21.31,1.28 ; HS1.MTG2 18.02,4.57 ; HS1.MTG2 23.69,6.95 ; HS1.MTG2 23.69,2.2 ; HS1.MTG2 18.93,2.2 ; 81.85,34.63 JP8.2 ; JP8.2 81.58,35.46 ; JP8.2 83.5,34.63 ; JP8.2 83.5,36.28 ; JP8.2 81.85,36.28 ; JP8.2 83.77,35.46 ; JP4.3 67.97,33.82 ; JP4.3 67.7,34.64 ; JP4.3 66.05,34.64 ; JP4.3 66.88,32.73 ; JP4.3 66.05,33 ; JP4.3 65.79,33.82 ; JP4.3 67.7,33 ; 134.82,16.69 J15.MT1 ; J15.MT1 137.34,14.26 ; J15.MT1 137.34,19.11 ; J15.MT1 136.08,19.11 ; J15.MT1 137.34,16.69 ; J15.MT1 136.08,14.26 ; J15.MT1 134.82,14.26 ; 19.36,46.69 TP6.1 ; TP6.1 20.27,48.82 ; TP6.1 20.27,46.38 ; TP6.1 21.49,47.6 ; TP6.1 21.18,46.69 ; TP6.1 19.05,47.6 ; TP6.1 21.18,48.51 ; TP6.1 19.36,48.51 ; TP8.1 44.15,50.95 ; TP8.1 45.06,50.65 ; TP8.1 42.93,49.73 ; TP8.1 45.36,49.73 ; TP8.1 45.06,48.82 ; TP8.1 44.15,48.51 ; TP8.1 43.23,48.82 ; TP8.1 43.23,50.65 ; J12.4 61.23,45.97 ; J12.4 57.9,45.97 ; J12.4 60.79,44.75 ; J12.4 59.56,44.31 ; J12.4 58.34,47.2 ; J12.4 58.34,44.75 ; J12.4 59.56,47.64 ; J12.4 60.79,47.2 ; TP14.1 76.99,45.77 ; TP14.1 75.16,45.77 ; TP14.1 75.16,43.94 ; TP14.1 76.07,43.64 ; TP14.1 77.29,44.86 ; TP14.1 76.99,43.94 ; TP14.1 76.07,46.08 ; TP14.1 74.85,44.86 ; JP2.3 82.47,10.58 ; JP2.3 80.56,11.4 ; JP2.3 82.21,11.4 ; JP2.3 80.29,10.58 ; JP2.3 81.38,9.49 ; JP2.3 82.21,9.75 ; JP2.3 80.56,9.75 ; 119.2,45.82 TP9.1 ; TP9.1 120.42,47.04 ; TP9.1 121.33,44.91 ; TP9.1 120.42,44.6 ; TP9.1 119.51,46.73 ; TP9.1 121.64,45.82 ; TP9.1 121.33,46.73 ; TP9.1 119.51,44.91 ; 78.73,50.05 JP3.2 ; JP3.2 78.73,48.4 ; JP3.2 78.46,49.23 ; JP3.2 80.65,49.23 ; JP3.2 80.38,50.05 ; JP3.2 80.38,48.4 ; 54.48,44.31 J12.5 ; J12.5 54.48,47.64 ; J12.5 53.26,47.2 ; J12.5 52.82,45.97 ; J12.5 55.71,47.2 ; J12.5 56.15,45.97 ; J12.5 55.71,44.75 ; J12.5 53.26,44.75 ; 151.99,0.76 TP11.1 ; TP11.1 153.18,1.18 ; TP11.1 150.81,3.54 ; TP11.1 150.81,1.18 ; TP11.1 153.18,3.54 ; TP11.1 150.39,2.36 ; TP11.1 153.59,2.36 ; TP11.1 151.99,3.96 ; J38.2 113.37,32.45 ; J38.2 111.62,32.45 ; J38.2 112.5,34.49 ; J38.2 111.33,33.32 ; J38.2 113.37,34.2 ; J38.2 112.5,32.16 ; J38.2 113.67,33.32 ; J38.2 111.62,34.2 ; MT1.1 10,14.73 ; MT1.1 7.98,12.71 ; MT1.1 9.45,16.21 ; MT1.1 6.5,13.25 ; MT1.1 5.96,14.73 ; MT1.1 7.98,16.75 ; MT1.1 6.5,16.21 ; MT1.1 9.45,13.25 ; 150.75,64.82 TP1.1 ; TP1.1 150.75,66.65 ; TP1.1 152.58,66.65 ; TP1.1 152.88,65.74 ; TP1.1 150.44,65.74 ; TP1.1 151.66,64.52 ; TP1.1 152.58,64.82 ; TP1.1 151.66,66.95 ; JP7.2 82.14,42.37 ; JP7.2 80.23,43.19 ; JP7.2 80.23,41.54 ; JP7.2 81.87,43.19 ; JP7.2 79.96,42.37 ; JP7.2 81.87,41.54 ; HS1.MTG1 19.24,45.05 ; HS1.MTG1 16.87,45.96 ; HS1.MTG1 20.16,42.67 ; HS1.MTG1 16.87,39.38 ; HS1.MTG1 13.58,42.67 ; HS1.MTG1 14.49,45.05 ; HS1.MTG1 14.49,40.3 ; HS1.MTG1 19.24,40.3 ; MT2.1 9.74,65.53 ; MT2.1 7.72,63.51 ; MT2.1 6.24,64.05 ; MT2.1 6.24,67.01 ; MT2.1 9.2,64.05 ; MT2.1 5.7,65.53 ; MT2.1 7.72,67.55 ; MT2.1 9.2,67.01 ; J15.5 131.66,17.16 ; J15.5 131.66,18.81 ; J15.5 130.01,17.16 ; J15.5 130.84,16.89 ; J15.5 130.01,18.81 ; J15.5 130.84,19.08 ; 88.27,16.56 TP7.1 ; TP7.1 89.18,18.69 ; TP7.1 87.35,16.87 ; TP7.1 89.18,16.87 ; TP7.1 88.27,19 ; TP7.1 89.48,17.78 ; TP7.1 87.35,18.69 ; TP7.1 87.05,17.78 ; 67.53,40 JP5.1 ; JP5.1 68.35,41.92 ; JP5.1 67.53,42.19 ; JP5.1 66.44,41.1 ; JP5.1 66.71,40.27 ; JP5.1 68.35,40.27 ; JP5.1 66.71,41.92 ; J17.2 138.49,7.62 ; J17.2 139.94,5.19 ; J17.2 137.05,2.75 ; J17.2 139.94,7.62 ; J17.2 137.05,5.19 ; J17.2 138.49,2.75 ; J17.2 139.94,2.75 ; JP1.3 79.41,9.75 ; JP1.3 79.41,11.4 ; JP1.3 77.76,11.4 ; JP1.3 77.76,9.75 ; JP1.3 77.49,10.58 ; JP1.3 79.68,10.58 ; JP1.3 78.59,9.49
  L8_SIG w0.406: 92.4,35.87 MT3.1 ; MT3.1 93.88,36.41 ; MT3.1 95.36,32.91 ; MT3.1 93.88,32.37 ; MT3.1 92.4,32.91 ; MT3.1 95.36,35.87 ; MT3.1 91.86,34.39 ; MT3.1 95.9,34.39
  L8_SIG w0.432: MT2.1 9.2,64.05 ; MT2.1 6.24,64.05 ; MT2.1 7.72,67.55 ; MT2.1 5.7,65.53 ; MT2.1 9.2,67.01 ; MT2.1 9.74,65.53 ; MT2.1 7.72,63.51 ; MT2.1 6.24,67.01 ; J15.MT2 130.05,16.69 ; J15.MT2 127.53,14.26 ; J15.MT2 128.79,19.11 ; J15.MT2 127.53,19.11 ; J15.MT2 127.53,16.69 ; J15.MT2 130.05,19.11 ; J15.MT2 128.79,14.26 ; JP1.3 79.68,10.58 ; JP1.3 78.59,9.49 ; JP1.3 77.76,11.4 ; JP1.3 77.49,10.58 ; JP1.3 79.41,9.75 ; JP1.3 77.76,9.75 ; JP1.3 79.41,11.4 ; J15.5 130.84,19.08 ; J15.5 130.01,18.81 ; J15.5 130.84,16.89 ; J15.5 131.66,17.16 ; J15.5 130.01,17.16 ; J15.5 131.66,18.81 ; J12.2 54.48,52.72 ; J12.2 53.26,49.83 ; J12.2 56.15,51.05 ; J12.2 53.26,52.28 ; J12.2 52.82,51.05 ; J12.2 54.48,49.39 ; J12.2 55.71,49.83 ; J12.2 55.71,52.28 ; 80.56,11.4 JP2.3 ; JP2.3 82.21,11.4 ; JP2.3 82.21,9.75 ; JP2.3 82.47,10.58 ; JP2.3 80.29,10.58 ; JP2.3 81.38,9.49 ; JP2.3 80.56,9.75 ; 138.49,2.75 J17.2 ; J17.2 139.94,7.62 ; J17.2 137.05,5.19 ; J17.2 139.94,2.75 ; J17.2 139.94,5.19 ; J17.2 137.05,2.75 ; J17.2 138.49,7.62 ; MT1.1 10,14.73 ; MT1.1 9.45,16.21 ; MT1.1 6.5,16.21 ; MT1.1 7.98,12.71 ; MT1.1 6.5,13.25 ; MT1.1 7.98,16.75 ; MT1.1 5.96,14.73 ; MT1.1 9.45,13.25 ; 18.93,6.95 HS1.MTG2 ; HS1.MTG2 23.69,2.2 ; HS1.MTG2 21.31,7.86 ; HS1.MTG2 23.69,6.95 ; HS1.MTG2 21.31,1.28 ; HS1.MTG2 24.6,4.57 ; HS1.MTG2 18.02,4.57 ; HS1.MTG2 18.93,2.2 ; 20.27,46.38 TP6.1 ; TP6.1 19.36,48.51 ; TP6.1 21.18,46.69 ; TP6.1 20.27,48.82 ; TP6.1 19.36,46.69 ; TP6.1 21.18,48.51 ; TP6.1 19.05,47.6 ; TP6.1 21.49,47.6 ; 111.33,33.32 J38.2 ; J38.2 113.37,32.45 ; J38.2 113.37,34.2 ; J38.2 113.67,33.32 ; J38.2 112.5,32.16 ; J38.2 111.62,34.2 ; J38.2 111.62,32.45 ; J38.2 112.5,34.49 ; 150.81,3.54 TP11.1 ; TP11.1 153.18,3.54 ; TP11.1 151.99,0.76 ; TP11.1 153.59,2.36 ; TP11.1 151.99,3.96 ; TP11.1 150.39,2.36 ; TP11.1 150.81,1.18 ; TP11.1 153.18,1.18 ; 66.44,41.1 JP5.1 ; JP5.1 66.71,40.27 ; JP5.1 67.53,42.19 ; JP5.1 67.53,40 ; JP5.1 68.35,41.92 ; JP5.1 66.71,41.92 ; JP5.1 68.35,40.27 ; 57.9,45.97 J12.4 ; J12.4 61.23,45.97 ; J12.4 60.79,47.2 ; J12.4 58.34,47.2 ; J12.4 59.56,47.64 ; J12.4 59.56,44.31 ; J12.4 60.79,44.75 ; J12.4 58.34,44.75 ; J17.3 137.24,10.22 ; J17.3 134.35,5.35 ; J17.3 135.79,5.35 ; J17.3 134.35,10.22 ; J17.3 134.35,7.79 ; J17.3 137.24,7.79 ; J17.3 135.79,10.22 ; 43.23,48.82 TP8.1 ; TP8.1 45.06,48.82 ; TP8.1 45.36,49.73 ; TP8.1 45.06,50.65 ; TP8.1 43.23,50.65 ; TP8.1 44.15,50.95 ; TP8.1 44.15,48.51 ; TP8.1 42.93,49.73 ; HS1.MTG1 16.87,45.96 ; HS1.MTG1 16.87,39.38 ; HS1.MTG1 19.24,45.05 ; HS1.MTG1 13.58,42.67 ; HS1.MTG1 14.49,40.3 ; HS1.MTG1 19.24,40.3 ; HS1.MTG1 20.16,42.67 ; HS1.MTG1 14.49,45.05 ; 57.9,51.05 J12.3 ; J12.3 60.79,49.83 ; J12.3 60.79,52.28 ; J12.3 61.23,51.05 ; J12.3 58.34,52.28 ; J12.3 58.34,49.83 ; J12.3 59.56,52.72 ; J15.MT1 137.34,19.11 ; J15.MT1 136.08,14.26 ; J15.MT1 134.82,14.26 ; J15.MT1 137.34,16.69 ; J15.MT1 136.08,19.11 ; J15.MT1 137.34,14.26 ; TP14.1 76.07,46.08 ; TP14.1 77.29,44.86 ; TP14.1 75.16,45.77 ; TP14.1 74.85,44.86 ; TP14.1 76.99,45.77 ; JP3.2 80.65,49.23 ; JP3.2 80.38,50.05 ; JP3.2 78.46,49.23 ; JP3.2 80.38,48.4 ; JP3.2 78.73,50.05 ; JP3.2 78.73,48.4 ; 119.51,44.91 TP9.1 ; TP9.1 120.42,44.6 ; TP9.1 119.51,46.73 ; TP9.1 119.2,45.82 ; TP9.1 121.33,44.91 ; TP9.1 121.64,45.82 ; TP9.1 121.33,46.73 ; TP9.1 120.42,47.04 ; TP7.1 89.18,18.69 ; TP7.1 87.05,17.78 ; TP7.1 88.27,16.56 ; TP7.1 88.27,19 ; TP7.1 89.18,16.87 ; TP7.1 87.35,18.69 ; TP7.1 87.35,16.87 ; TP7.1 89.48,17.78 ; 150.44,65.74 TP1.1 ; TP1.1 151.66,66.95 ; TP1.1 150.75,64.82 ; TP1.1 150.75,66.65 ; TP1.1 152.88,65.74 ; TP1.1 151.66,64.52 ; TP1.1 152.58,64.82 ; TP1.1 152.58,66.65 ; J12.5 55.71,47.2 ; J12.5 53.26,47.2 ; J12.5 54.48,44.31 ; J12.5 52.82,45.97 ; J12.5 53.26,44.75 ; J12.5 55.71,44.75 ; J12.5 54.48,47.64 ; J12.5 56.15,45.97 ; 5.31,9.8 TP2.1 ; TP2.1 6.53,8.58 ; TP2.1 5.61,8.89 ; TP2.1 7.75,9.8 ; TP2.1 7.44,8.89 ; TP2.1 6.53,11.02 ; TP2.1 5.61,10.72 ; TP2.1 7.44,10.72 ; JP8.2 83.5,36.28 ; JP8.2 81.58,35.46 ; JP8.2 81.85,34.63 ; JP8.2 83.5,34.63 ; JP8.2 81.85,36.28 ; JP8.2 83.77,35.46
  L9_GND w0.406: MT3.1 95.9,34.39 ; MT3.1 95.36,35.87 ; MT3.1 93.88,36.41 ; MT3.1 92.4,32.91 ; MT3.1 93.88,32.37 ; MT3.1 92.4,35.87 ; MT3.1 91.86,34.39 ; MT3.1 95.36,32.91
  L9_GND w0.432: 127.53,16.69 J15.MT2 ; J15.MT2 127.53,19.11 ; J15.MT2 127.53,14.26 ; J15.MT2 130.05,16.69 ; J15.MT2 130.05,19.11 ; J15.MT2 128.79,19.11 ; J15.MT2 128.79,14.26 ; JP2.3 82.47,10.58 ; JP2.3 80.56,11.4 ; JP2.3 80.56,9.75 ; JP2.3 82.21,9.75 ; JP2.3 82.21,11.4 ; JP2.3 80.29,10.58 ; JP2.3 81.38,9.49 ; 6.24,64.05 MT2.1 ; MT2.1 9.2,67.01 ; MT2.1 9.74,65.53 ; MT2.1 7.72,63.51 ; MT2.1 9.2,64.05 ; MT2.1 6.24,67.01 ; MT2.1 7.72,67.55 ; MT2.1 5.7,65.53 ; 87.35,18.69 TP7.1 ; TP7.1 89.18,16.87 ; TP7.1 87.35,16.87 ; TP7.1 88.27,19 ; TP7.1 89.18,18.69 ; TP7.1 88.27,16.56 ; TP7.1 89.48,17.78 ; TP7.1 87.05,17.78 ; MT1.1 9.45,13.25 ; MT1.1 9.45,16.21 ; MT1.1 6.5,16.21 ; MT1.1 7.98,12.71 ; MT1.1 6.5,13.25 ; MT1.1 10,14.73 ; MT1.1 7.98,16.75 ; MT1.1 5.96,14.73 ; TP8.1 45.06,48.82 ; TP8.1 45.36,49.73 ; TP8.1 45.06,50.65 ; TP8.1 42.93,49.73 ; TP8.1 44.15,50.95 ; TP8.1 44.15,48.51 ; TP8.1 43.23,50.65 ; TP8.1 43.23,48.82 ; JP8.2 83.5,34.63 ; JP8.2 83.5,36.28 ; JP8.2 81.58,35.46 ; JP8.2 81.85,36.28 ; JP8.2 81.85,34.63 ; JP8.2 83.77,35.46 ; TP1.1 152.58,66.65 ; TP1.1 152.58,64.82 ; TP1.1 151.66,66.95 ; TP1.1 151.66,64.52 ; TP1.1 152.88,65.74 ; TP1.1 150.44,65.74 ; TP1.1 150.75,66.65 ; TP1.1 150.75,64.82 ; 58.34,44.75 J12.4 ; J12.4 58.34,47.2 ; J12.4 61.23,45.97 ; J12.4 59.56,44.31 ; J12.4 60.79,47.2 ; J12.4 57.9,45.97 ; J12.4 60.79,44.75 ; J12.4 59.56,47.64 ; 80.23,41.54 JP7.2 ; JP7.2 81.87,41.54 ; JP7.2 81.87,43.19 ; JP7.2 80.23,43.19 ; JP7.2 79.96,42.37 ; JP7.2 82.14,42.37 ; 6.53,8.58 TP2.1 ; TP2.1 5.31,9.8 ; TP2.1 6.53,11.02 ; TP2.1 7.75,9.8 ; TP2.1 5.61,10.72 ; TP2.1 7.44,8.89 ; TP2.1 5.61,8.89 ; TP2.1 7.44,10.72 ; HS1.MTG1 19.24,45.05 ; HS1.MTG1 13.58,42.67 ; HS1.MTG1 14.49,45.05 ; HS1.MTG1 19.24,40.3 ; HS1.MTG1 16.87,39.38 ; HS1.MTG1 14.49,40.3 ; HS1.MTG1 16.87,45.96 ; HS1.MTG1 20.16,42.67 ; TP9.1 121.64,45.82 ; TP9.1 120.42,44.6 ; TP9.1 120.42,47.04 ; TP9.1 121.33,46.73 ; TP9.1 119.51,44.91 ; TP9.1 119.2,45.82 ; TP9.1 119.51,46.73 ; TP9.1 121.33,44.91 ; J12.5 55.71,47.2 ; J12.5 54.48,47.64 ; J12.5 56.15,45.97 ; J12.5 55.71,44.75 ; J12.5 52.82,45.97 ; J12.5 54.48,44.31 ; J12.5 53.26,47.2 ; J12.5 53.26,44.75 ; J17.2 139.94,7.62 ; J17.2 137.05,2.75 ; J17.2 138.49,7.62 ; J17.2 138.49,2.75 ; J17.2 139.94,5.19 ; J17.2 137.05,5.19 ; J17.2 139.94,2.75 ; HS1.MTG2 23.69,2.2 ; HS1.MTG2 18.02,4.57 ; HS1.MTG2 18.93,2.2 ; HS1.MTG2 23.69,6.95 ; HS1.MTG2 21.31,7.86 ; HS1.MTG2 18.93,6.95 ; HS1.MTG2 21.31,1.28 ; HS1.MTG2 24.6,4.57 ; J15.MT1 137.34,19.11 ; J15.MT1 137.34,14.26 ; J15.MT1 137.34,16.69 ; J15.MT1 136.08,14.26 ; J15.MT1 134.82,14.26 ; J15.MT1 136.08,19.11 ; J15.MT1 134.82,16.69 ; JP5.1 68.35,40.27 ; JP5.1 66.44,41.1 ; JP5.1 66.71,41.92 ; JP5.1 68.35,41.92 ; JP5.1 66.71,40.27 ; JP5.1 67.53,40 ; JP5.1 67.53,42.19 ; 134.35,5.35 J17.3 ; J17.3 135.79,10.22 ; J17.3 137.24,10.22 ; J17.3 135.79,5.35 ; J17.3 134.35,7.79 ; J17.3 134.35,10.22 ; J17.3 137.24,7.79 ; TP14.1 76.99,45.77 ; TP14.1 77.29,44.86 ; TP14.1 75.16,43.94 ; TP14.1 76.07,43.64 ; TP14.1 76.99,43.94 ; TP14.1 76.07,46.08 ; TP14.1 75.16,45.77 ; TP14.1 74.85,44.86 ; 20.27,46.38 TP6.1 ; TP6.1 20.27,48.82 ; TP6.1 19.05,47.6 ; TP6.1 19.36,48.51 ; TP6.1 21.18,48.51 ; TP6.1 21.49,47.6 ; TP6.1 21.18,46.69 ; TP6.1 19.36,46.69 ; 111.62,34.2 J38.2 ; J38.2 113.37,32.45 ; J38.2 113.37,34.2 ; J38.2 112.5,34.49 ; J38.2 113.67,33.32 ; J38.2 112.5,32.16 ; J38.2 111.33,33.32 ; J38.2 111.62,32.45 ; 78.46,49.23 JP3.2 ; JP3.2 78.73,50.05 ; JP3.2 80.65,49.23 ; JP3.2 80.38,48.4 ; JP3.2 78.73,48.4 ; JP3.2 80.38,50.05 ; 130.01,18.81 J15.5 ; J15.5 130.84,16.89 ; J15.5 130.01,17.16 ; J15.5 131.66,17.16 ; J15.5 131.66,18.81 ; J15.5 130.84,19.08 ; 65.79,33.82 JP4.3 ; JP4.3 66.88,32.73 ; JP4.3 66.05,34.64 ; JP4.3 66.05,33 ; JP4.3 67.7,33 ; JP4.3 67.7,34.64 ; JP4.3 67.97,33.82 ; JP1.3 79.68,10.58 ; JP1.3 77.76,9.75 ; JP1.3 78.59,9.49 ; JP1.3 79.41,9.75 ; JP1.3 77.49,10.58 ; JP1.3 79.41,11.4 ; JP1.3 77.76,11.4 ; 58.34,49.83 J12.3 ; J12.3 60.79,52.28 ; J12.3 59.56,52.72 ; J12.3 60.79,49.83 ; J12.3 61.23,51.05 ; J12.3 57.9,51.05 ; J12.3 58.34,52.28 ; 150.81,3.54 TP11.1 ; TP11.1 153.18,3.54 ; TP11.1 151.99,0.76 ; TP11.1 150.81,1.18 ; TP11.1 153.59,2.36 ; TP11.1 153.18,1.18 ; TP11.1 151.99,3.96 ; TP11.1 150.39,2.36 ; 53.26,52.28 J12.2 ; J12.2 54.48,49.39 ; J12.2 56.15,51.05 ; J12.2 55.71,52.28 ; J12.2 55.71,49.83 ; J12.2 54.48,52.72 ; J12.2 52.82,51.05 ; J12.2 53.26,49.83
  L10_PWR_SIG w0.406: 92.4,32.91 MT3.1 ; MT3.1 93.88,32.37 ; MT3.1 95.36,35.87 ; MT3.1 95.36,32.91 ; MT3.1 93.88,36.41 ; MT3.1 95.9,34.39 ; MT3.1 91.86,34.39 ; MT3.1 92.4,35.87
  L10_PWR_SIG w0.432: HS1.MTG1 20.16,42.67 ; HS1.MTG1 19.24,40.3 ; HS1.MTG1 19.24,45.05 ; HS1.MTG1 13.58,42.67 ; HS1.MTG1 14.49,40.3 ; HS1.MTG1 16.87,45.96 ; HS1.MTG1 16.87,39.38 ; HS1.MTG1 14.49,45.05 ; 21.31,1.28 HS1.MTG2 ; HS1.MTG2 23.69,2.2 ; HS1.MTG2 24.6,4.57 ; HS1.MTG2 18.93,6.95 ; HS1.MTG2 18.02,4.57 ; HS1.MTG2 18.93,2.2 ; TP2.1 6.53,11.02 ; TP2.1 7.44,10.72 ; TP2.1 7.75,9.8 ; TP2.1 5.61,10.72 ; TP2.1 5.61,8.89 ; TP2.1 7.44,8.89 ; TP2.1 6.53,8.58 ; TP2.1 5.31,9.8 ; JP1.3 79.41,11.4 ; JP1.3 79.68,10.58 ; JP1.3 78.59,9.49 ; JP1.3 79.41,9.75 ; JP1.3 77.49,10.58 ; JP1.3 77.76,9.75 ; JP1.3 77.76,11.4 ; MT2.1 9.2,67.01 ; MT2.1 9.2,64.05 ; MT2.1 6.24,64.05 ; MT2.1 7.72,67.55 ; MT2.1 7.72,63.51 ; MT2.1 6.24,67.01 ; MT2.1 9.74,65.53 ; MT2.1 5.7,65.53 ; 57.9,45.97 J12.4 ; J12.4 59.56,44.31 ; J12.4 60.79,47.2 ; J12.4 58.34,47.2 ; J12.4 61.23,45.97 ; J12.4 59.56,47.64 ; J12.4 60.79,44.75 ; J12.4 58.34,44.75 ; TP8.1 45.06,50.65 ; TP8.1 45.06,48.82 ; TP8.1 44.15,50.95 ; TP8.1 45.36,49.73 ; TP8.1 43.23,48.82 ; TP8.1 42.93,49.73 ; TP8.1 44.15,48.51 ; TP8.1 43.23,50.65 ; 87.05,17.78 TP7.1 ; TP7.1 87.35,18.69 ; TP7.1 87.35,16.87 ; TP7.1 88.27,16.56 ; TP7.1 89.48,17.78 ; TP7.1 89.18,16.87 ; TP7.1 88.27,19 ; TP7.1 89.18,18.69 ; TP6.1 21.18,46.69 ; TP6.1 19.05,47.6 ; TP6.1 21.49,47.6 ; TP6.1 21.18,48.51 ; TP6.1 19.36,46.69 ; TP6.1 20.27,46.38 ; TP6.1 19.36,48.51 ; TP6.1 20.27,48.82 ; J12.2 54.48,52.72 ; J12.2 53.26,52.28 ; J12.2 55.71,49.83 ; J12.2 53.26,49.83 ; J12.2 56.15,51.05 ; J12.2 52.82,51.05 ; J12.2 54.48,49.39 ; J12.2 55.71,52.28 ; J12.5 54.48,47.64 ; J12.5 53.26,44.75 ; J12.5 55.71,44.75 ; J12.5 54.48,44.31 ; J12.5 53.26,47.2 ; J12.5 52.82,45.97 ; J12.5 55.71,47.2 ; J12.5 56.15,45.97 ; J17.3 137.24,10.22 ; J17.3 135.79,10.22 ; J17.3 134.35,7.79 ; J17.3 137.24,7.79 ; J17.3 135.79,5.35 ; J17.3 134.35,10.22 ; J17.3 134.35,5.35 ; TP11.1 153.18,1.18 ; TP11.1 150.39,2.36 ; TP11.1 151.99,0.76 ; TP11.1 150.81,1.18 ; TP11.1 150.81,3.54 ; TP11.1 153.59,2.36 ; TP11.1 153.18,3.54 ; TP11.1 151.99,3.96 ; 134.82,14.26 J15.MT1 ; J15.MT1 136.08,14.26 ; J15.MT1 134.82,16.69 ; J15.MT1 136.08,19.11 ; J15.MT1 137.34,14.26 ; J15.MT1 137.34,19.11 ; J15.MT1 137.34,16.69 ; J12.3 59.56,52.72 ; J12.3 57.9,51.05 ; J12.3 58.34,52.28 ; J12.3 58.34,49.83 ; 127.53,16.69 J15.MT2 ; J15.MT2 130.05,19.11 ; J15.MT2 127.53,19.11 ; J15.MT2 127.53,14.26 ; J15.MT2 128.79,19.11 ; J15.MT2 130.05,16.69 ; J15.MT2 128.79,14.26 ; 150.75,64.82 TP1.1 ; TP1.1 151.66,66.95 ; TP1.1 152.58,64.82 ; TP1.1 150.44,65.74 ; TP1.1 152.88,65.74 ; TP1.1 150.75,66.65 ; TP1.1 152.58,66.65 ; TP1.1 151.66,64.52 ; 6.5,16.21 MT1.1 ; MT1.1 7.98,16.75 ; MT1.1 5.96,14.73 ; MT1.1 6.5,13.25 ; MT1.1 7.98,12.71 ; 138.49,2.75 J17.2 ; J17.2 139.94,2.75 ; J17.2 137.05,2.75 ; J17.2 139.94,5.19 ; J17.2 139.94,7.62 ; J17.2 137.05,5.19 ; J17.2 138.49,7.62 ; 130.84,16.89 J15.5 ; J15.5 131.66,17.16 ; J15.5 130.01,18.81 ; J15.5 131.66,18.81 ; J15.5 130.84,19.08 ; J15.5 130.01,17.16 ; JP2.3 82.47,10.58 ; JP2.3 81.38,9.49 ; JP2.3 80.56,11.4 ; JP2.3 82.21,9.75 ; JP2.3 80.29,10.58 ; JP2.3 80.56,9.75 ; JP2.3 82.21,11.4 ; 74.89,44.35 TP14.1 ; TP14.1 74.85,44.86 ; TP14.1 75.16,43.94 ; TP14.1 75.16,45.77 ; 119.51,44.91 TP9.1 ; TP9.1 121.64,45.82 ; TP9.1 119.2,45.82 ; TP9.1 120.42,44.6 ; TP9.1 121.33,44.91 ; J38.2 113.64,33.81 ; J38.2 113.37,34.2 ; J38.2 113.64,32.84 ; J38.2 113.67,33.32
  L11_GND w0.406: MT3.1 93.88,36.41 ; MT3.1 95.36,32.91 ; MT3.1 95.36,35.87 ; MT3.1 93.88,32.37 ; MT3.1 95.9,34.39 ; MT3.1 92.4,32.91 ; MT3.1 91.86,34.39 ; MT3.1 92.4,35.87
  L11_GND w0.432: JP2.3 82.21,9.75 ; JP2.3 81.38,9.49 ; JP2.3 82.47,10.58 ; JP2.3 80.56,11.4 ; JP2.3 80.29,10.58 ; JP2.3 80.56,9.75 ; JP2.3 82.21,11.4 ; J38.2 113.37,32.45 ; J38.2 111.33,33.32 ; J38.2 113.67,33.32 ; J38.2 112.5,32.16 ; J38.2 111.62,34.2 ; J38.2 112.5,34.49 ; J38.2 113.37,34.2 ; J38.2 111.62,32.45 ; 18.02,4.57 HS1.MTG2 ; HS1.MTG2 18.93,6.95 ; HS1.MTG2 21.31,1.28 ; HS1.MTG2 23.69,2.2 ; HS1.MTG2 21.31,7.86 ; HS1.MTG2 24.6,4.57 ; HS1.MTG2 23.69,6.95 ; HS1.MTG2 18.93,2.2 ; 75.16,45.77 TP14.1 ; TP14.1 76.07,46.08 ; TP14.1 75.16,43.94 ; TP14.1 74.85,44.86 ; TP14.1 76.99,45.77 ; TP14.1 77.29,44.86 ; TP14.1 76.99,43.94 ; TP14.1 76.07,43.64 ; J12.3 60.79,52.28 ; J12.3 60.79,49.83 ; J12.3 57.9,51.05 ; J12.3 58.34,49.83 ; J12.3 58.34,52.28 ; J12.3 59.56,52.72 ; J12.3 61.23,51.05 ; J15.5 131.66,17.16 ; J15.5 130.84,19.08 ; J15.5 131.66,18.81 ; J15.5 130.01,17.16 ; J15.5 130.84,16.89 ; J15.5 130.01,18.81 ; TP2.1 7.75,9.8 ; TP2.1 7.44,8.89 ; TP2.1 6.53,8.58 ; TP2.1 7.44,10.72 ; TP2.1 5.61,10.72 ; TP2.1 5.61,8.89 ; TP2.1 5.31,9.8 ; TP2.1 6.53,11.02 ; MT2.1 9.2,67.01 ; MT2.1 9.74,65.53 ; MT2.1 9.2,64.05 ; MT2.1 6.24,64.05 ; MT2.1 5.7,65.53 ; MT2.1 7.72,67.55 ; MT2.1 7.72,63.51 ; MT2.1 6.24,67.01 ; 65.79,33.82 JP4.3 ; JP4.3 67.97,33.82 ; JP4.3 67.7,34.64 ; JP4.3 66.05,33 ; JP4.3 66.05,34.64 ; JP4.3 66.88,32.73 ; JP4.3 67.7,33 ; 6.5,16.21 MT1.1 ; MT1.1 6.5,13.25 ; MT1.1 9.45,16.21 ; MT1.1 5.96,14.73 ; MT1.1 7.98,12.71 ; MT1.1 9.45,13.25 ; MT1.1 10,14.73 ; MT1.1 7.98,16.75 ; 20.27,46.38 TP6.1 ; TP6.1 21.18,48.51 ; TP6.1 19.36,46.69 ; TP6.1 20.27,48.82 ; TP6.1 21.18,46.69 ; TP6.1 21.49,47.6 ; TP6.1 19.05,47.6 ; TP6.1 19.36,48.51 ; TP1.1 152.88,65.74 ; TP1.1 152.58,64.82 ; TP1.1 152.58,66.65 ; TP1.1 151.66,64.52 ; TP1.1 150.75,66.65 ; TP1.1 150.75,64.82 ; TP1.1 150.44,65.74 ; TP1.1 151.66,66.95 ; TP9.1 121.33,44.91 ; TP9.1 119.51,44.91 ; TP9.1 119.51,46.73 ; TP9.1 121.33,46.73 ; TP9.1 121.64,45.82 ; TP9.1 120.42,47.04 ; TP9.1 120.42,44.6 ; TP9.1 119.2,45.82 ; 77.49,10.58 JP1.3 ; JP1.3 78.59,9.49 ; JP1.3 77.76,11.4 ; JP1.3 77.76,9.75 ; JP1.3 79.41,11.4 ; JP1.3 79.68,10.58 ; JP1.3 79.41,9.75 ; 150.81,1.18 TP11.1 ; TP11.1 151.99,0.76 ; TP11.1 153.59,2.36 ; TP11.1 151.99,3.96 ; TP11.1 150.39,2.36 ; TP11.1 153.18,1.18 ; TP11.1 153.18,3.54 ; TP11.1 150.81,3.54 ; HS1.MTG1 19.24,40.3 ; HS1.MTG1 20.16,42.67 ; HS1.MTG1 19.24,45.05 ; HS1.MTG1 16.87,39.38 ; HS1.MTG1 13.58,42.67 ; HS1.MTG1 14.49,40.3 ; HS1.MTG1 16.87,45.96 ; HS1.MTG1 14.49,45.05 ; 81.85,34.63 JP8.2 ; JP8.2 81.58,35.46 ; JP8.2 83.5,34.63 ; JP8.2 81.85,36.28 ; JP8.2 83.5,36.28 ; JP8.2 83.77,35.46 ; J12.2 54.48,52.72 ; J12.2 53.26,52.28 ; J12.2 52.82,51.05 ; J12.2 55.71,49.83 ; J12.2 54.48,49.39 ; J12.2 53.26,49.83 ; J12.2 56.15,51.05 ; J12.2 55.71,52.28 ; 87.35,18.69 TP7.1 ; TP7.1 89.48,17.78 ; TP7.1 87.35,16.87 ; TP7.1 89.18,18.69 ; TP7.1 88.27,19 ; TP7.1 89.18,16.87 ; TP7.1 87.05,17.78 ; TP7.1 88.27,16.56 ; JP3.2 80.65,49.23 ; JP3.2 80.38,48.4 ; JP3.2 78.46,49.23 ; JP3.2 78.73,48.4 ; JP3.2 80.38,50.05 ; JP3.2 78.73,50.05 ; 134.82,16.69 J15.MT1 ; J15.MT1 137.34,14.26 ; J15.MT1 134.82,14.26 ; J15.MT1 136.08,14.26 ; J15.MT1 137.34,19.11 ; J15.MT1 136.08,19.11 ; J15.MT1 137.34,16.69 ; J12.5 56.15,45.97 ; J12.5 55.71,44.75 ; J12.5 52.82,45.97 ; J12.5 54.48,47.64 ; J12.5 55.71,47.2 ; J12.5 53.26,47.2 ; J12.5 54.48,44.31 ; J12.5 53.26,44.75 ; 128.79,14.26 J15.MT2 ; J15.MT2 130.05,16.69 ; J15.MT2 127.53,14.26 ; J15.MT2 127.53,16.69 ; J15.MT2 130.05,19.11 ; J15.MT2 128.79,19.11 ; J15.MT2 127.53,19.11 ; J12.4 60.79,44.75 ; J12.4 59.56,44.31 ; J12.4 58.34,47.2 ; J12.4 61.23,45.97 ; J12.4 58.34,44.75 ; J12.4 57.9,45.97 ; J12.4 59.56,47.64 ; J12.4 60.79,47.2 ; JP7.2 82.14,42.37 ; JP7.2 81.87,43.19 ; JP7.2 79.96,42.37 ; JP7.2 81.87,41.54 ; JP7.2 80.23,41.54 ; JP7.2 80.23,43.19 ; J17.2 139.94,2.75 ; J17.2 137.05,2.75 ; J17.2 137.05,5.19 ; J17.2 138.49,7.62 ; J17.2 139.94,5.19 ; J17.2 139.94,7.62 ; J17.2 138.49,2.75 ; 44.15,48.51 TP8.1 ; TP8.1 44.15,50.95 ; TP8.1 45.06,50.65 ; TP8.1 42.93,49.73 ; TP8.1 43.23,50.65 ; TP8.1 45.06,48.82 ; TP8.1 45.36,49.73 ; TP8.1 43.23,48.82 ; 135.79,5.35 J17.3 ; J17.3 134.35,5.35 ; J17.3 134.35,7.79 ; J17.3 137.24,10.22 ; J17.3 137.24,7.79 ; J17.3 134.35,10.22 ; J17.3 135.79,10.22 ; JP5.1 68.35,40.27 ; JP5.1 66.44,41.1 ; JP5.1 67.53,40 ; JP5.1 68.35,41.92 ; JP5.1 66.71,41.92 ; JP5.1 66.71,40.27 ; JP5.1 67.53,42.19
  BOTTOM w0.102: 16.27,23.69 16.24,23.66 C85.2 C57.2 17.06,21.12 17.3,20.87 v1(17.45,20.87) ; C96.2 19.45,26.07 v1(19.05,25.67)
  BOTTOM w0.203: U5.2 71.06,43.2 v1(70.56,42.7)
  BOTTOM w0.254: v3(32.77,54.38) 32.79,54.36 C143.2 ; v2(32.1,62.49) 32.18,62.58 C119.2 ; C115.2 33.4,54.59 v2(33.41,54.6) ; 16.27,23.69 16.24,23.69 v1(15.85,24.07) ; v3(22.67,25.26) 22.76,25.35 22.76,25.98 C100.2 ; C114.2 34.8,54.53 v2(34.73,54.6) ; C120.2 33.4,62.5 v2(33.41,62.49) ; C88.2 18.41,20.22 17.7,20.22 C103.2 ; C146.2 v3(32.79,62.53) ; v2(34.73,62.49) 34.8,62.56 C121.2
  BOTTOM w0.305: v3(72.72,48.41) 72.35,48.41 U5.34 ; C39.2 22.17,23.35 v1(22.25,23.27) 22.25,22.74 C41.2 22.17,22.55 v1(22.25,22.47) ; C44.1 v1(18.25,24.87) ; v6(93.34,14.92) 93.61,14.66 93.78,14.66 93.78,14.67 v6(94.03,14.92) ; v1(105.18,43.18) 105.16,43.16 U10.13 102.27,43.16 v1(102.26,43.16) ; J14.G8 146.47,50.29 v1(146.76,50.58) ; C106.2 15.2,27.93 v1(15.05,28.07) ; 19.15,22.48 19.06,22.48 v1(19.05,22.47) ; 19.15,22.48 C34.2 ; 19.15,22.48 v1(19.05,22.47) ; C266.2 134.09,19.71 v1(134.11,19.68) ; v1(91.12,42.65) 91.13,42.65 v3(91.88,42.65) U10.35 ; 15.25,28.69 15.24,28.69 v1(15.05,28.87) ; v8(27.62,53.56) 27.4,53.78 C446.1 ; C82.2 17.43,20.85 v1(17.45,20.87) ; v1(102.31,44.65) 102.31,44.65 U10.10 104.86,44.65 104.95,44.56 104.95,44.27 104.86,44.18 104.86,44.19 v3(104.21,44.19) ; v1(146.76,48.62) 146.81,48.78 147.05,49.02 J14.F9 ; v1(19.05,24.07) 19.06,24.07 C33.2 ; C50.2 v1(22.25,24.87) ; v1(22.25,24.87) 22.64,25.26 v3(22.67,25.26) ; v1(22.25,24.87) 21.87,24.49 21.84,24.49 ; v1(87.76,38.12) 87.71,38.17 C260.1 ; C40.2 19.05,22.48 v1(19.05,22.47) ; v1(15.05,21.67) 15.19,21.81 15.25,21.81 ; J14.E11 v1(149.96,47.75) ; v1(15.05,20.87) 15.12,20.87 C81.2 ; C53.2 16.65,26.37 v1(16.65,26.47) ; U10.15 102.26,42.16 v1(102.26,42.15) ; v2(148.06,40.61) 147.42,41.25 J14.F15 ; v8(26.1,52.08) 25.91,52.27 C445.1 ; C58.2 17.45,24.07 v1(17.45,24.07) 17.45,24.08 C62.2 ; v6(89.28,8.6) 89.06,8.37 U19.5 ; J14.J8 143.94,50.29 v1(144.18,50.05) ; 70.05,43.1 70.06,43.11 70.06,43.46 70.03,43.49 70.03,43.93 70.06,43.97 U5.4 ; v1(141.55,39.01) 142.09,39.55 142.9,39.55 143.59,38.86 J14.J17 ; v1(86.03,38.12) 86.08,38.17 C261.2 ; v1(15.05,27.27) 15.04,27.25 C69.2 ; v1(107.29,15.75) 107.44,15.9 C359.2 ; v3(72.33,49.93) 72.33,50.14 v3(72.28,50.2) ; J14.B6 152.45,52.83 151.97,53.31 v2(151.87,53.31) ; v1(104.57,11.86) 104.78,12.06 C356.2 ; v1(14.25,26.47) 14.43,26.3 C74.2 ; J14.H15 v2(144.3,41.99) ; 18.36,23.27 18.36,23.27 v1(18.25,23.27) ; C267.2 v1(135.99,19.66) ; 15.28,22.62 v1(15.05,22.47) ; U19.6 89.31,9.02 U19.9 ; J14.H18 144.88,37.57 v2(145.26,37.19) ; 22.11,20.28 22.25,20.14 v1(22.25,20.07) 22.06,20.27 22.06,20.33 ; C65.2 15.88,26.45 v1(15.85,26.47) ; R331.1 21.72,27.81 v1(21.45,28.07) ; v1(17.45,20.07) 17.64,20.26 C103.2 ; v1(17.45,26.47) 17.45,26.47 C61.2 ; U10.11 102.33,44.16 v1(102.32,44.16) ; C73.2 14.44,24.26 v1(14.25,24.07) ; v1(44.37,1.4) 44.19,1.58 U15.2 44.19,3.6 v6(44.16,3.63) ; R50.1 37.58,54.38 v2(37.36,54.6) ; J14.G14 v1(146.76,42.06) ; v1(22.25,24.07) 21.84,24.49 ; 21.84,24.49 C38.2 ; U10.5 102.27,47.16 v1(102.26,47.15) ; C269.2 107.65,51.87 v1(107.94,51.57) ; v2(142.77,37.19) 142.37,37.59 J14.K18 ; C116.2 C143.2 ; v1(106.94,50.29) 107.24,49.99 C270.2 ; C49.2 v1(22.25,27.27) ; U10.1 v3(103.13,49.16) 102.28,49.16 v1(101.88,49.56)
  BOTTOM w0.381: v2(145.47,15.29) 144.91,14.73 J14.H36 ; v2(149.3,26.62) 148.69,27.23 J14.E26 v2(147.42,26.16) ; J14.B30 152.5,22.3 v2(151.89,21.69) ; J14.J35 143.56,16 v2(143.08,15.52) ; v1(151.94,44.53) 151.36,43.94 J14.C13 ; J14.G17 146.23,38.86 v2(146.81,39.45) ; v2(146.76,55.96) 146.18,55.37 J14.G4 ; v2(145.47,33.22) 144.91,33.78 J14.H21 ; v2(144.88,26.16) J14.G26 146.15,27.48 v2(146.66,27.99) ; v1(154.48,45.24) 154.46,45.21 J14.A12 ; v1(146.81,34.42) 147.42,33.81 J14.F21 J14.E20 J14.D19 149.96,36.3 v2(150.55,35.71) ; v2(150.57,33.12) J14.D22 J14.E23 J14.F24 147.42,30.02 v2(146.81,30.63) 146.2,31.24 J14.G23 146.15,31.39 v1(145.49,32.05) ; J14.H3 144.96,56.64 v2(145.57,57.25) ; J14.D3 v2(150.57,56.03) ; J14.D3 v2(149.38,57.23) ; J14.D3 149.28,55.96 149.28,55.93 148.72,55.37 J14.E4 ; v2(146.79,21.51) 146.79,21.62 147.42,22.25 J14.F30 ; v2(146.71,12.85) 146.15,12.29 J14.G38 ; v2(144.17,24.13) 143.66,23.62 J14.J29 v2(142.99,23) J14.K30 141.17,22.35 v1(140.74,22.78) ; J14.K3 142.29,56.64 v1(141.78,56.13) ; v1(149.07,53.75) 148.72,54.1 J14.E5 ; J14.J11 v2(144.2,47.07) ; J14.A33 v2(153.21,19.1) ; v2(149.4,25.5) 149.96,24.94 v2(149.96,24.89) ; v2(142.88,29.49) 142.39,29.97 J14.K24 ; J14.B26 152.5,27.46 v2(151.89,28.07) ; J14.H24 v2(145.49,29.36) ; v2(144.2,55.98) 143.61,55.4 J14.J4 ; J14.A16 v1(154.41,40.13) ; v2(153.14,11.61) 152.55,12.19 J14.B38 ; v1(152.5,47.75) v1(152.5,46.48) v1(151.23,45.21) ; J14.J26 J14.K27 142.37,26.16 v2(142.93,25.6) ; J14.B15 152.53,41.4 v2(153.16,42.04) ; J14.H9 v2(145.47,49.61) ; J14.B34 152.55,17.27 v2(153.14,16.69) ; J14.H12 144.91,45.21 v2(145.52,45.82) ; v2(153.19,24.18) 153.75,23.62 J14.A29 ; v1(141.73,14.17) 142.29,14.73 J14.K36 ; J14.H30 144.88,22.33 145.54,21.67 v2(145.54,21.59) ; v2(148.69,23.62) 148.79,23.62 v2(149.22,23.19) ; J14.F3 147.45,56.64 v2(148.03,57.23) ; J14.A37 v2(153.16,14.07) ; J14.A25 v2(153.16,29.31) ; v2(142.95,45.8) 142.37,45.21 J14.K12 ; v2(150.65,12.75) 151.21,12.19 J14.C38 ; J14.C16 151.28,40.13 v2(151.87,39.55) 151.23,38.91 J14.C17 v2(150.57,39.52) J14.D16 ; J14.E38 v2(149.3,12.8) ; J14.D13 149.99,43.94 v2(150.6,44.55) ; J14.G11 v2(146.74,47.07)
  BOTTOM w0.432: JP8.2 83.77,35.46 ; JP8.2 81.58,35.46 ; JP8.2 81.85,34.63 ; JP8.2 83.5,34.63 ; 5.61,8.89 TP2.1 ; TP2.1 6.53,11.02 ; TP2.1 7.75,9.8 ; TP2.1 6.53,8.58 ; TP2.1 7.44,8.89 ; TP2.1 7.44,10.72 ; TP2.1 5.61,10.72 ; TP2.1 5.31,9.8 ; 59.56,44.31 J12.4 ; J12.4 58.34,44.75 ; J12.4 61.23,45.97 ; J12.4 60.79,44.75 ; J12.4 60.79,47.2 ; J12.4 58.34,47.2 ; J12.4 57.9,45.97 ; J12.4 59.56,47.64 ; TP1.1 152.58,66.65 ; TP1.1 151.66,66.95 ; TP1.1 150.75,64.82 ; TP1.1 151.66,64.52 ; TP1.1 150.44,65.74 ; TP1.1 150.75,66.65 ; TP1.1 152.58,64.82 ; TP1.1 152.88,65.74 ; J12.5 55.71,47.2 ; J12.5 55.71,44.75 ; J12.5 53.26,44.75 ; J12.5 54.48,47.64 ; J12.5 53.26,47.2 ; J12.5 56.15,45.97 ; J12.5 54.48,44.31 ; J12.5 52.82,45.97 ; 18.02,4.57 HS1.MTG2 ; HS1.MTG2 23.69,6.95 ; HS1.MTG2 21.31,7.86 ; HS1.MTG2 18.93,6.95 ; HS1.MTG2 18.93,2.2 ; HS1.MTG2 23.69,2.2 ; HS1.MTG2 24.6,4.57 ; HS1.MTG2 21.31,1.28 ; J15.MT1 137.34,19.11 ; J15.MT1 136.08,14.26 ; J15.MT1 134.82,14.26 ; J15.MT1 136.08,19.11 ; J15.MT1 137.34,16.69 ; J15.MT1 137.34,14.26 ; J15.MT1 134.82,16.69 ; 14.49,40.3 HS1.MTG1 ; HS1.MTG1 16.87,39.38 ; HS1.MTG1 19.24,45.05 ; HS1.MTG1 13.58,42.67 ; HS1.MTG1 14.49,45.05 ; HS1.MTG1 20.16,42.67 ; HS1.MTG1 19.24,40.3 ; HS1.MTG1 16.87,45.96 ; TP6.1 21.18,46.69 ; TP6.1 19.36,48.51 ; TP6.1 19.36,46.69 ; TP6.1 21.49,47.6 ; TP6.1 21.18,48.51 ; TP6.1 19.05,47.6 ; TP6.1 20.27,46.38 ; TP6.1 20.27,48.82 ; TP7.1 88.27,19 ; TP7.1 89.48,17.78 ; TP7.1 87.35,16.87 ; TP7.1 89.18,18.69 ; TP7.1 89.18,16.87 ; TP7.1 87.05,17.78 ; TP7.1 88.27,16.56 ; TP7.1 87.35,18.69 ; 54.48,49.39 J12.2 ; J12.2 55.71,49.83 ; J12.2 56.15,51.05 ; J12.2 54.48,52.72 ; J12.2 52.82,51.05 ; J12.2 55.71,52.28 ; J12.2 53.26,52.28 ; J12.2 53.26,49.83 ; JP4.3 67.7,34.64 ; JP4.3 66.05,33 ; JP4.3 67.97,33.82 ; JP4.3 66.88,32.73 ; JP4.3 66.05,34.64 ; JP4.3 67.7,33 ; JP4.3 65.79,33.82 ; J15.MT2 128.79,19.11 ; J15.MT2 130.05,19.11 ; J15.MT2 128.79,14.26 ; J15.MT2 127.53,19.11 ; J15.MT2 130.05,16.69 ; J17.2 138.49,7.62 ; J17.2 139.94,2.75 ; J17.2 137.05,2.75 ; J17.2 139.94,7.62 ; J17.2 139.94,5.19 ; J17.2 138.49,2.75 ; J17.2 137.05,5.19 ; TP9.1 121.33,44.91 ; TP9.1 121.64,45.82 ; TP9.1 119.51,44.91 ; TP9.1 120.42,44.6 ; TP9.1 119.51,46.73 ; TP9.1 121.33,46.73 ; TP9.1 119.2,45.82 ; TP9.1 120.42,47.04 ; J38.2 112.5,34.49 ; J38.2 113.67,33.32 ; J38.2 113.37,32.45 ; J38.2 111.33,33.32 ; J38.2 112.5,32.16 ; J38.2 113.37,34.2 ; J38.2 111.62,34.2 ; J38.2 111.62,32.45 ; JP2.3 82.21,11.4 ; JP2.3 80.56,11.4 ; JP2.3 80.29,10.58 ; JP2.3 82.47,10.58 ; TP8.1 45.06,48.82 ; TP8.1 43.23,50.65 ; TP8.1 45.06,50.65 ; TP8.1 43.23,48.82 ; TP8.1 45.36,49.73 ; TP8.1 42.93,49.73 ; TP8.1 44.15,50.95 ; TP8.1 44.15,48.51 ; 75.16,43.94 TP14.1 ; TP14.1 76.07,43.64 ; TP14.1 74.85,44.86 ; TP14.1 76.99,43.94 ; TP14.1 76.99,45.77 ; TP14.1 77.29,44.86 ; TP14.1 75.16,45.77 ; TP14.1 76.07,46.08 ; 67.53,40 JP5.1 ; JP5.1 68.62,40 ; JP5.1 68.62,42.19 ; JP5.1 66.44,40 ; JP5.1 66.44,41.1 ; 130.01,18.81 J15.5 ; J15.5 130.84,16.89 ; J15.5 130.01,17.16 ; J15.5 131.66,17.16 ; J15.5 130.84,19.08 ; J15.5 131.66,18.81 ; 78.46,49.23 JP3.2 ; JP3.2 80.38,50.05 ; JP3.2 80.65,49.23 ; JP3.2 80.38,48.4 ; JP3.2 78.73,50.05 ; JP3.2 78.73,48.4 ; 151.99,0.76 TP11.1 ; TP11.1 150.81,3.54 ; TP11.1 153.59,2.36 ; TP11.1 151.99,3.96 ; TP11.1 150.81,1.18 ; TP11.1 153.18,3.54 ; TP11.1 150.39,2.36 ; TP11.1 153.18,1.18 ; 57.9,51.05 J12.3 ; J12.3 58.34,49.83 ; J12.3 60.79,52.28 ; J12.3 61.23,51.05 ; J12.3 59.56,52.72 ; J12.3 58.34,52.28 ; J12.3 60.79,49.83 ; J17.3 137.24,7.79 ; J17.3 135.79,10.22 ; J17.3 135.79,5.35 ; J17.3 137.24,10.22 ; JP1.3 79.68,10.58 ; JP1.3 79.41,11.4 ; JP1.3 77.76,11.4 ; JP1.3 79.05,11.65 ; 80.23,41.54 JP7.2 ; JP7.2 80.23,43.19 ; JP7.2 80.59,41.3 ; JP7.2 79.96,42.37
  vias: v1(0.56,0.69) v1(0.74,66.29) v1(0.74,40.13) v1(0.74,37.72) v1(0.84,25.78) v1(0.84,24.66) v1(0.86,54.48) v1(0.86,52.07) v1(0.97,13.21) v1(0.97,12.09) v1(0.97,7.21) v1(0.99,5.23) v1(1.3,61.32) v1(1.3,59.31) v1(1.35,47.35) v1(1.3,45.34) v1(1.55,32.64) v1(1.5,19.91) v1(1.6,30.63) v1(1.57,17.93) v1(2.29,0.69) v1(2.49,7.24) v1(2.51,5.26) v1(2.74,45.34) v1(2.79,61.34) v1(2.84,59.31) v1(2.82,47.32) v1(2.79,25.27) v1(2.92,12.7) v1(3.17,32.64) v1(3.23,30.63) v1(3.17,19.91) v1(3.3,17.93) v1(3.4,53.21) v1(3.53,66.29) v1(3.91,0.69) v1(3.96,7.21) v1(3.99,5.23) v1(4.24,47.35) v1(4.24,45.36) v1(4.29,61.34) v1(4.34,59.36) v1(4.75,32.56) v1(4.78,30.68) v1(4.83,19.89) v1(4.83,18.01) v1(4.83,16.03) v1(4.85,25.35) v1(4.98,12.78) v1(5.03,0.69) v1(5.08,2.54) v1(5.18,49.66) v1(5.26,41.43) v1(5.33,34.75) v1(5.38,57.58) v1(5.36,55.3) v1(5.44,7.24) v1(5.41,5.21) v1(5.51,47.27) v1(5.51,45.39) v1(6.07,61.24) v1(6.15,59.39) v1(6.1,36.65) v1(6.07,22.48) v1(6.22,0.64) v1(6.3,19.86) v1(6.32,18.01) v1(6.45,43.31) v1(6.45,32.59) v1(6.48,30.71) v1(6.48,28.65) v1(6.6,47.29) v1(6.63,33.6) v1(6.63,29.74) v1(6.6,7.29) v1(6.68,27.41) v1(6.81,49.68) v1(6.86,45.44) v1(6.99,5.46) v1(7.14,34.95) v1(7.42,18.01) v1(7.49,61.47) v1(7.49,20.02) v1(7.57,7.9) v1(7.62,2.54) v1(7.87,47.35) v1(8.03,59.66) v1(7.95,0.64) v1(8.2,45.39) v1(8.21,29.77) v1(8.18,25.86) v1(8.2,24.16) v1(8.2,22.61) v1(8.2,20.77) v1(8.2,18.24) v1(8.26,28.32) v1(8.36,41.43) v1(8.38,36.17) v1(8.38,11.35) v1(8.43,8.74) v1(8.56,6.3) v1(8.79,62.13) v1(8.86,32.94) v1(8.86,18.41) v1(9.12,47.32) v1(9.35,37.11) v1(9.4,9.68) v1(9.63,43.31) v1(9.58,0.64) v1(9.83,63.09) v1(9.78,45.42) v1(9.75,7.42) v1(9.88,60.58) v1(10.03,24.18) v1(10.14,27.86) v1(10.11,22.7) v1(10.13,19.74) v1(10.08,17.14) v1(10.16,5.08) v1(10.16,2.54) v1(10.34,55.85) v1(10.29,47.6) v1(10.29,38.1) v1(10.29,26.39) v1(10.39,10.69) v1(10.59,32.26) v1(10.59,25.1) v1(10.69,0.64) v1(10.77,8.41) v1(10.9,66.42) v1(10.87,64.14) v1(10.87,56.36) v1(10.9,30.51) v1(10.97,45.69) v1(11,34.37) v1(11.07,61.72) v1(11.17,18.44) v1(11.33,57.12) v1(11.3,15.95) v1(11.43,48.08) v1(11.43,11.76) v1(11.53,41.4) v1(11.48,24.13) v1(11.53,14.48) v1(11.63,54.31) v1(11.66,20.93) v1(11.66,20.32) v1(11.76,9.42) v1(11.91,58.65) v1(11.94,57.73) v1(12.01,65.28) v1(12.01,43.31) v1(12.01,35.46) v1(12.14,62.76) v1(12.06,0.66) v1(12.22,28.78) v1(12.19,25.98) v1(12.17,21.79) v1(12.34,59.59) v1(12.29,54.99) v1(12.32,46.25) v1(12.34,12.65) v1(12.37,48.84) v1(12.52,29.97) v1(12.7,38.99) v1(12.7,37.34) v1(12.7,7.62) v1(12.7,5.08) v1(12.7,2.54) v1(12.83,25.4) v1(12.8,10.49) v1(12.85,55.68) v1(12.85,44.7) v1(12.9,17.81) v1(13,28.17) v1(12.98,26.37) v1(13.08,66.32) v1(13.06,13.39) v1(13.16,63.8) v1(13.16,60.22) v1(13.16,18.69) v1(13.28,49.78) v1(13.26,40.69) v1(13.31,33.88) v1(13.51,56.34) v1(13.46,25.58) v1(13.46,24.97) v1(13.51,16.84) v1(13.51,14.96) v1(13.56,47.32) v1(13.72,11.38) v1(13.69,0.66) v1(13.79,58.29) v1(13.77,57.63) v1(14,67.26) v1(14.05,31.88) v1(14.15,45.36) v1(14.12,38.96) v1(14.22,64.82) v1(14.22,37.34) v1(14.3,50.88) v1(14.25,28.87) v1(14.25,28.07) v1(14.25,22.47) v1(14.43,12.09) v1(14.63,60.55) v1(14.61,48.46) v1(14.66,58.32) v1(14.68,32.99) v1(14.81,0.66) v1(15.05,23.27) v1(15.05,20.07) v1(15.24,65.86) v1(15.24,51.89) v1(15.19,13.18) v1(15.24,7.62) v1(15.24,5.08) v1(15.24,2.54) v1(15.57,58.29) v1(15.72,60.55) v1(15.67,39.01) v1(15.82,64.19) v1(15.77,49.12) v1(15.8,46.99) v1(15.88,37.34) v1(16.03,53.98) v1(15.98,35.56) v1(15.98,33.78) v1(16.1,11) v1(16.1,8.41) v1(16.33,58.17) v1(16.28,14.91) v1(16.59,61.82) v1(16.65,24.07) v1(16.69,0.76) v1(16.87,65.91) v1(16.87,65.15) v1(16.87,51.94) v1(16.87,51.18) v1(16.97,49.15) v1(16.97,18.19) v1(17.17,60.55) v1(17.17,55.78) v1(17.53,53.92) v1(17.6,35.56) v1(17.65,38.94) v1(17.65,37.29) v1(17.83,63.17) v1(17.78,5.08) v1(17.78,2.54) v1(17.88,47.12) v1(18.24,49.12) v1(18.25,26.47) v1(18.39,60.55) v1(18.52,65.53) v1(18.52,55.73) v1(18.47,51.59) v1(18.52,0.79) v1(18.8,33.96) v1(19.02,61.85) v1(19.08,53.95) v1(19.05,47.09) v1(19.05,37.31) v1(19.13,35.61) v1(19.05,28.87) v1(19.25,63.17) v1(19.33,49.17) v1(19.28,40.18) v1(19.48,60.53) v1(19.61,55.73) v1(19.79,31.11) v1(19.79,16.23) v1(19.86,33.99) v1(19.85,28.07) v1(19.86,19.46) v1(20.09,51.59) v1(20.07,45.85) v1(20.09,44.12) v1(20.12,17.65) v1(20.22,65.51) v1(20.45,57.68) v1(20.42,38.79) v1(20.5,60.5) v1(20.47,58.62) v1(20.52,41.48) v1(20.55,36.3) v1(20.6,55.85) v1(20.7,35.41) v1(20.73,31.98) v1(20.65,28.07) v1(20.73,0.74) v1(20.78,63.12) v1(20.8,49.17) v1(20.93,53.95) v1(21.03,33.96) v1(21.08,58.39) v1(21.21,62.1) v1(21.21,61.19) v1(21.44,56.24) v1(21.44,14.48) v1(21.54,42.47) v1(21.49,39.93) v1(21.74,55.32) v1(21.77,37.62) v1(22,49.17) v1(22.05,47.29) v1(22,17.65) v1(22.07,36.45) v1(22.2,44.53) v1(22.23,43.26) v1(22.28,63.12) v1(22.25,28.07) v1(22.4,53.98) v1(22.35,35.41) v1(22.35,34.04) v1(23.01,56.41) v1(23.09,60.58) v1(23.06,58.75) v1(23.24,58.01) v1(23.34,17.53) v1(23.27,0.74) v1(23.6,63.17) v1(23.62,61.93) v1(23.7,49.15) v1(23.7,47.52) v1(23.8,38.89) v1(23.77,37.24) v1(24.03,42.37) v1(24.1,33.71) v1(24.17,53.95) v1(24.21,35.46) v1(24.38,24.49) v1(24.41,19.58) v1(24.41,18.08) v1(24.51,29.36) v1(24.54,27.66) v1(24.49,26.06) v1(24.61,40.36) v1(24.61,22.89) v1(24.74,62) v1(24.82,63.12) v1(24.92,37.8) v1(24.94,16.1) v1(25.02,34.39) v1(25.2,45.9) v1(25.22,8.69) v1(25.4,2.54) v1(25.58,0.76) v1(25.71,55.47) v1(25.83,44.2) v1(25.81,39.22) v1(25.91,63.17) v1(25.91,56.62) v1(26.02,59.15) v1(25.98,17.07) v1(26.24,26.09) v1(26.24,22.89) v1(26.21,21.31) v1(26.24,8.69) v1(26.29,36.65) v1(26.31,27.71) v1(26.26,24.46) v1(26.34,18.67) v1(26.47,61.19) v1(26.54,49.28) v1(26.54,46.23) v1(26.54,12.7) v1(26.75,65.53) v1(26.75,33.53) v1(26.7,29.41) v1(26.92,56.16) v1(26.97,40.41) v1(27,38.46) v1(27.3,8.46) v1(27.36,62.05) v1(27.43,44.42) v1(27.43,42.54) v1(27.38,19.71) v1(27.53,36.58) v1(27.74,0.74) v1(27.99,65.51) v1(28.07,41.4) v1(28.12,24.56) v1(28.27,35.41) v1(28.45,12.73) v1(28.4,8.46) v1(28.57,40.41) v1(28.57,38.53) v1(28.57,29.41) v1(28.57,22.96) v1(28.68,63.47) v1(28.69,46.31) v1(28.69,44.43) v1(28.65,27.84) v1(28.78,33.81) v1(28.85,67.64) v1(28.88,26.16) v1(28.91,19.71) v1(28.88,1.47) v1(28.98,18.69) v1(29.01,0.74) v1(29.06,12.04) v1(29.18,38.51) v1(29.18,36.63) v1(29.26,50.34) v1(29.33,44.43) v1(29.34,42.54) v1(29.46,52.98) v1(29.46,12.75) v1(29.64,64.39) v1(29.64,41.99) v1(29.62,18.69) v1(30.12,42.65) v1(30.1,5.69) v1(30.23,41.05) v1(30.28,0.74) v1(30.53,29.41) v1(30.51,27.81) v1(30.53,26.24) v1(30.53,19.71) v1(30.53,12.34) v1(30.56,24.56) v1(30.56,23.01) v1(30.84,53.01) v1(30.81,18.75) v1(30.94,1.01) v1(31.24,5.18) v1(31.5,64.41) v1(31.55,0.74) v1(31.65,12.37) v1(31.8,18.9) v1(32.18,49.48) v1(32.21,34.3) v1(32.44,35.31) v1(32.59,5.18) v1(32.69,22.96) v1(32.74,21.31) v1(32.74,19.1) v1(32.79,24.59) v1(32.82,0.74) v1(32.89,31.06) v1(32.94,29.44) v1(32.87,27.81) v1(32.92,26.21) v1(33.22,50.47) v1(33.71,19.1) v1(33.71,5.23) v1(33.92,50.39) v1(33.92,48.35) v1(33.96,22.96) v1(34.01,21.31) v1(34.11,34.3) v1(34.06,24.59) v1(34.09,0.74) v1(34.49,4.7) v1(34.85,31.06) v1(34.85,29.44) v1(34.82,26.21) v1(34.9,27.84) v1(34.87,19.63) v1(35.23,22.96) v1(35.23,5.84) v1(35.33,24.59) v1(35.28,21.31) v1(35.36,0.74) v1(35.84,50.37) v1(35.83,48.36) v1(35.86,49) v1(36.04,27.81) v1(36.07,31.06) v1(36.09,26.21) v1(36.14,19.63) v1(36.2,5.84) v1(36.5,22.96) v1(36.6,24.59) v1(36.55,21.31) v1(36.63,0.74) v1(36.65,29.44) v1(37.14,34.73) v1(37.34,31.06) v1(37.31,27.81) v1(37.36,26.21) v1(37.41,19.63) v1(37.74,49) v1(37.74,4.88) v1(37.77,22.96) v1(37.82,21.31) v1(37.77,3.2) v1(37.8,1.7) v1(37.87,24.59) v1(37.9,0.74) v1(38.3,4.09) v1(38.48,14.68) v1(38.58,27.81) v1(38.63,26.21) v1(38.61,3.17) v1(38.61,1.7) v1(38.68,19.63) v1(38.73,12.34) v1(38.89,13.59) v1(39.05,34.73) v1(39.04,22.96) v1(39.14,24.59) v1(39.09,21.31) v1(39.24,31.09) v1(39.17,0.74) v1(39.72,34.72) v1(39.93,29.44) v1(39.85,27.81) v1(39.9,26.21) v1(39.95,49.83) v1(39.95,19.63) v1(40.01,12.09) v1(40.31,22.96) v1(40.41,24.59) v1(40.36,21.31) v1(40.44,0.74) v1(41.15,31.06) v1(41.12,27.81) v1(41.15,5.13) v1(41.2,29.44) v1(41.17,26.21) v1(41.22,19.63) v1(41.27,12.09) v1(41.62,34.72) v1(41.58,22.96) v1(41.63,21.31) v1(41.68,24.59) v1(41.71,0.74) v1(41.91,4.6) v1(42.01,7.24) v1(42.06,32.79) v1(42.39,27.81) v1(42.44,26.21) v1(42.47,29.44) v1(42.49,19.63) v1(42.85,22.96) v1(42.9,21.31) v1(42.93,7.24) v1(42.95,24.59) v1(42.98,0.74) v1(43.33,32.79) v1(43.28,31.09) v1(43.38,42.65) v1(43.36,42.06) v1(43.36,40.61) v1(43.74,29.44) v1(43.66,27.81) v1(43.71,26.21) v1(43.76,19.63) v1(44.12,22.96) v1(44.17,44.27) v1(44.22,24.59) v1(44.17,21.31) v1(44.25,0.74) v1(44.63,32.69) v1(44.65,34.8) v1(44.7,12.57) v1(44.93,27.81) v1(44.96,31.06) v1(45.01,29.44) v1(44.98,26.21) v1(45.03,19.63) v1(45.24,42.57) v1(45.24,40.69) v1(45.39,22.96) v1(45.44,21.31) v1(45.49,24.59) v1(45.52,0.74) v1(45.9,32.69) v1(46.01,36.5) v1(46.01,34.62) v1(45.97,5) v1(46.23,31.06) v1(46.2,27.81) v1(46.23,12.19) v1(46.28,29.44) v1(46.25,26.21) v1(46.3,19.63) v1(46.74,42.67) v1(46.66,22.96) v1(46.71,21.31) v1(46.76,40.67) v1(46.76,24.59) v1(46.79,4.47) v1(46.79,0.74) v1(47.17,32.69) v1(47.5,31.06) v1(47.55,29.44) v1(47.47,27.81) v1(47.52,26.21) v1(47.57,19.63) v1(47.7,46) v1(47.89,36.5) v1(47.89,34.62) v1(47.93,22.96) v1(48.03,24.59) v1(47.98,21.31) v1(48.06,0.74) v1(48.34,42.49) v1(48.41,46.79) v1(48.36,40.72) v1(48.44,32.69) v1(48.74,27.81) v1(48.77,31.06) v1(48.82,29.44) v1(48.79,26.21) v1(48.84,19.63) v1(48.92,44.09) v1(48.95,37.64) v1(49.2,22.96) v1(49.33,47.68) v1(49.3,24.59) v1(49.25,21.31) v1(49.33,0.74) v1(49.38,45.47) v1(49.71,32.69) v1(49.94,5.33) v1(50.04,43.51) v1(50.01,36.58) v1(50.01,27.81) v1(50.11,41.63) v1(50.14,34.49) v1(50.06,31.09) v1(50.14,29.46) v1(50.06,26.21) v1(50.11,19.63) v1(50.34,46.43) v1(50.5,48.51) v1(50.47,22.96) v1(50.52,21.31) v1(50.57,24.59) v1(50.6,0.74) v1(50.98,32.69) v1(51,6.35) v1(51.23,47.09) v1(51.26,43.54) v1(51.28,41.68) v1(51.31,31.06) v1(51.28,27.81) v1(51.33,26.21) v1(51.36,29.44) v1(51.38,19.63) v1(51.64,36.5) v1(51.64,34.62) v1(51.74,22.96) v1(51.84,24.59) v1(51.79,21.31) v1(51.87,0.74) v1(51.99,49.12) v1(52.25,32.69) v1(52.4,47.55) v1(52.58,31.06) v1(52.63,29.44) v1(52.55,27.81) v1(52.6,26.21) v1(52.65,19.63) v1(53.01,22.96) v1(53.01,12.42) v1(53.06,43.46) v1(53.06,41.68) v1(53.11,24.59) v1(53.06,21.31) v1(53.14,0.74) v1(53.52,32.69) v1(53.85,31.06) v1(53.82,27.81) v1(53.85,6.32) v1(53.92,49.3) v1(53.9,29.44) v1(53.87,26.21) v1(53.92,19.63) v1(53.9,12.45) v1(54.1,47.78) v1(54.28,22.96) v1(54.33,21.31) v1(54.38,24.59) v1(54.41,0.74) v1(54.48,40.82) v1(54.71,43.48) v1(54.79,41.68) v1(54.91,32.74) v1(54.91,12.42) v1(55.12,40.82) v1(55.12,31.06) v1(55.09,27.81) v1(55.14,26.21) v1(55.17,29.44) v1(55.19,19.63) v1(55.55,22.96) v1(55.6,21.31) v1(55.65,24.59) v1(55.68,0.74) v1(55.75,40.82) v1(55.8,11.91) v1(55.85,10.92) v1(55.85,9.4) v1(56.08,43.46) v1(56.13,41.68) v1(56.26,32.66) v1(56.39,40.82) v1(56.39,31.06) v1(56.44,29.44) v1(56.36,27.81) v1(56.41,26.21) v1(56.46,19.63) v1(56.52,12.34) v1(56.46,6.35) v1(56.67,10.92) v1(56.67,9.42) v1(56.82,22.96) v1(56.92,24.59) v1(56.87,21.31) v1(56.95,0.74) v1(57.28,12.04) v1(57.25,8.05) v1(57.38,43.46) v1(57.38,41.68) v1(57.53,32.66) v1(57.63,27.81) v1(57.66,31.06) v1(57.71,29.44) v1(57.68,26.21) v1(57.73,19.63) v1(58.09,22.96) v1(58.14,21.31) v1(58.19,24.59) v1(58.22,0.74) v1(58.62,12.04) v1(58.78,43.48) v1(58.8,41.68) v1(58.8,32.66) v1(58.93,31.06) v1(58.9,27.81) v1(58.98,29.44) v1(58.95,26.21) v1(59,19.63) v1(59.36,22.96) v1(59.41,21.31) v1(59.46,24.59) v1(59.49,0.74) v1(59.69,6.35) v1(60.07,32.66) v1(60.17,43.48) v1(60.22,41.66) v1(60.2,31.06) v1(60.25,29.44) v1(60.17,27.81) v1(60.22,26.21) v1(60.2,11.71) v1(60.27,19.63) v1(60.4,35.08) v1(60.63,22.96) v1(60.73,24.59) v1(60.68,21.31) v1(60.76,0.74) v1(60.99,12.19) v1(61.34,32.66) v1(61.44,27.81) v1(61.42,6.88) v1(61.48,51.9) v1(61.47,31.06) v1(61.52,29.44) v1(61.49,26.21) v1(61.54,19.63) v1(61.9,22.96) v1(61.98,43.46) v1(62,24.59) v1(61.95,21.31) v1(62,11.79) v1(62.03,0.74) v1(62.05,41.68) v1(62.36,34.59) v1(62.61,32.66) v1(62.74,31.06) v1(62.71,27.81) v1(62.8,49.72) v1(62.79,29.44) v1(62.76,26.21) v1(62.81,19.63) v1(62.89,40.84) v1(62.97,53.14) v1(63.17,22.96) v1(63.22,21.31) v1(63.27,24.59) v1(63.3,0.74) v1(63.6,44.58) v1(63.78,12.06) v1(63.93,43.48) v1(63.88,32.66) v1(63.98,41.68) v1(63.96,34.57) v1(64.01,31.06) v1(63.98,27.81) v1(64.03,26.21) v1(64.06,29.44) v1(64.08,19.63) v1(64.44,22.96) v1(64.54,24.59) v1(64.49,21.31) v1(64.57,0.74) v1(65.15,32.66) v1(65.3,43.48) v1(65.28,31.06) v1(65.33,29.44) v1(65.25,27.81) v1(65.3,26.21) v1(65.38,41.68) v1(65.35,19.63) v1(65.58,34.59) v1(65.58,13.94) v1(65.71,22.96) v1(65.81,24.59) v1(65.76,21.31) v1(65.84,0.74) v1(66.55,31.06) v1(66.52,27.81) v1(66.6,29.44) v1(66.57,26.21) v1(66.62,19.63) v1(66.75,12.09) v1(66.98,22.96) v1(67.03,21.31) v1(67.08,24.59) v1(67.11,0.74) v1(67.26,6.81) v1(67.39,13.94) v1(67.82,31.06) v1(67.79,27.81) v1(67.84,26.21) v1(67.87,29.44) v1(67.89,19.63) v1(68.25,22.96) v1(68.3,21.31) v1(68.35,24.59) v1(68.38,0.74) v1(69.09,31.06) v1(69.14,29.44) v1(69.06,27.81) v1(69.11,26.21) v1(69.09,12.17) v1(69.16,19.63) v1(69.52,22.96) v1(69.62,24.59) v1(69.57,21.31) v1(69.65,0.74) v1(70.08,7.75) v1(70.08,6.83) v1(70.21,12.14) v1(70.33,27.81) v1(70.36,31.06) v1(70.41,29.44) v1(70.38,26.21) v1(70.43,19.63) v1(70.79,22.96) v1(70.84,21.31) v1(70.89,24.59) v1(70.92,0.74) v1(70.99,8.66) v1(71.07,12.14) v1(71.63,31.06) v1(71.6,27.81) v1(71.55,6.93) v1(71.68,29.44) v1(71.65,26.21) v1(71.7,19.63) v1(72.06,22.96) v1(72.11,21.31) v1(72.16,24.59) v1(72.19,0.74) v1(72.9,31.06) v1(72.95,29.44) v1(72.87,27.81) v1(72.92,26.21) v1(72.97,19.63) v1(73,13.77) v1(72.97,6.35) v1(73.33,22.96) v1(73.43,24.59) v1(73.38,21.31) v1(73.46,0.74) v1(74.14,27.81) v1(74.17,31.06) v1(74.22,29.44) v1(74.19,26.21) v1(74.24,19.63) v1(74.45,6.96) v1(74.6,22.96) v1(74.7,24.59) v1(74.65,21.31) v1(74.73,0.74) v1(75.44,31.06) v1(75.41,27.81) v1(75.49,29.44) v1(75.46,26.21) v1(75.51,19.63) v1(75.84,13.79) v1(75.87,22.96) v1(75.92,21.31) v1(75.97,24.59) v1(76,0.74) v1(76.45,6.27) v1(76.71,31.06) v1(76.68,27.81) v1(76.73,26.21) v1(76.76,29.44) v1(76.78,19.63) v1(77.14,22.96) v1(77.24,24.59) v1(77.19,21.31) v1(77.27,0.74) v1(77.88,49.23) v1(77.98,31.06) v1(78.03,29.44) v1(77.95,27.81) v1(78,26.21) v1(78.05,19.63) v1(78.41,22.96) v1(78.51,24.59) v1(78.46,21.31) v1(78.54,0.74) v1(78.77,6.25) v1(79.25,31.06) v1(79.22,27.81) v1(79.3,29.44) v1(79.27,26.21) v1(79.32,19.63) v1(79.38,42.37) v1(79.68,22.96) v1(79.73,21.31) v1(79.78,24.59) v1(79.81,0.74) v1(80.01,13.16) v1(80.52,31.06) v1(80.49,27.81) v1(80.54,26.21) v1(80.57,29.44) v1(80.59,19.63) v1(80.62,6.38) v1(80.95,22.96) v1(81,21.31) v1(81.05,24.59) v1(81.08,0.74) v1(81.2,35.48) v1(81.41,5.84) v1(81.79,31.06) v1(81.84,29.44) v1(81.76,27.81) v1(81.81,26.21) v1(81.86,19.63) v1(82.22,22.96) v1(82.32,24.59) v1(82.27,21.31) v1(82.35,0.74) v1(82.8,13.77) v1(83.03,27.81) v1(83.06,31.06) v1(83.11,29.44) v1(83.08,26.21) v1(83.13,19.63) v1(83.49,22.96) v1(83.54,21.31) v1(83.59,24.59) v1(83.62,0.74) v1(83.69,11.73) v1(84.1,31.06) v1(84.07,27.81) v1(84.12,26.21) v1(84.15,29.44) v1(84.15,8.26) v1(84.15,7.44) v1(84.25,39.32) v1(84.4,19.63) v1(84.56,49.23) v1(84.76,22.96) v1(84.81,21.31) v1(84.89,32.74) v1(84.86,24.59) v1(84.89,0.74) v1(85.6,31.06) v1(85.65,29.44) v1(85.57,27.81) v1(85.62,26.21) v1(85.67,19.63) v1(85.7,8.26) v1(85.67,7.47) v1(85.83,40.94) v1(86.03,37.26) v1(86.03,36.4) v1(86.03,35.46) v1(86.03,22.96) v1(86.13,24.59) v1(86.08,21.31) v1(86.16,0.74) v1(86.51,50.85) v1(86.51,49.99) v1(86.51,49.12) v1(86.51,48.26) v1(86.5,44.76) v1(86.5,43.84) v1(86.5,42.98) v1(86.56,39.95) v1(86.64,18.41) v1(86.56,8.59) v1(86.84,32.77) v1(86.84,27.81) v1(86.89,38.12) v1(86.89,37.26) v1(86.89,36.4) v1(86.89,35.46) v1(86.87,31.06) v1(86.92,29.44) v1(86.89,26.21) v1(86.94,19.63) v1(86.92,6.5) v1(87.3,22.96) v1(87.33,15.7) v1(87.33,14.17) v1(87.38,50.85) v1(87.38,49.99) v1(87.38,49.12) v1(87.38,48.26) v1(87.36,44.76) v1(87.36,43.84) v1(87.36,42.98) v1(87.36,42.07) v1(87.4,24.59) v1(87.35,21.31) v1(87.35,8.08) v1(87.6,0.71) v1(87.76,37.26) v1(87.76,36.4) v1(87.76,35.46) v1(87.76,13.39) v1(87.99,32.77) v1(88.11,27.81) v1(88.11,15.7) v1(88.11,14.2) v1(88.24,50.85) v1(88.24,49.99) v1(88.24,49.12) v1(88.24,48.26) v1(88.22,44.76) v1(88.22,43.84) v1(88.22,42.98) v1(88.19,29.44) v1(88.16,26.21) v1(88.21,19.63) v1(88.37,7.06) v1(88.54,9.04) v1(88.57,22.96) v1(88.62,21.31) v1(88.67,24.59) v1(88.93,34.21) v1(88.87,6.3) v1(88.87,0.71) v1(89.15,31.06) v1(89.38,27.81) v1(89.43,26.21) v1(89.46,29.44) v1(89.48,19.63) v1(89.84,22.96) v1(89.94,24.59) v1(89.89,21.31) v1(90.04,18.52) v1(90.14,0.71) v1(90.17,13.34) v1(90.27,51.54) v1(90.42,31.06) v1(90.73,29.44) v1(90.65,27.81) v1(90.7,26.21) v1(90.73,16.56) v1(90.75,19.63) v1(91.11,22.96) v1(91.06,11.51) v1(91.21,24.59) v1(91.16,21.31) v1(91.41,0.71) v1(91.54,49.78) v1(91.49,17.09) v1(91.69,31.06) v1(91.92,27.81) v1(92,29.44) v1(91.97,26.21) v1(92.02,19.63) v1(92.3,50.29) v1(92.38,22.96) v1(92.43,21.31) v1(92.49,40.51) v1(92.48,24.59) v1(92.46,18.9) v1(92.68,0.71) v1(93.01,18.08) v1(93.22,31.06) v1(93.29,19.63) v1(93.43,39.8) v1(93.65,22.96) v1(93.7,21.31) v1(93.85,46.14) v1(93.95,0.71) v1(94.16,49.57) v1(94.49,31.06) v1(94.54,29.44) v1(94.46,27.81) v1(94.51,26.21) v1(94.56,19.63) v1(94.76,49.57) v1(94.77,41.33) v1(94.92,22.96) v1(95.02,24.59) v1(94.97,21.31) v1(95.22,0.71) v1(95.73,27.81) v1(95.76,31.06) v1(95.81,29.44) v1(95.78,26.21) v1(95.83,19.63) v1(96.19,22.96) v1(96.24,21.31) v1(96.29,24.59) v1(96.47,8.89) v1(96.49,0.71) v1(96.85,13.72) v1(97.03,31.06) v1(97,27.81) v1(97.08,29.44) v1(97.05,26.21) v1(97.1,19.63) v1(97.38,41.37) v1(97.46,22.96) v1(97.51,21.31) v1(97.56,24.59) v1(97.76,49.6) v1(97.76,0.71) v1(98.21,43.48) v1(98.22,42.66) v1(98.3,31.06) v1(98.35,29.44) v1(98.27,27.81) v1(98.32,26.21) v1(98.37,19.63) v1(98.58,35.13) v1(98.73,22.96) v1(98.83,24.59) v1(98.78,21.31) v1(98.93,45.21) v1(99.03,0.71) v1(99.24,12.95) v1(99.29,6.73) v1(99.54,27.81) v1(99.57,31.06) v1(99.62,29.44) v1(99.59,26.21) v1(99.64,19.63) v1(99.77,35.05) v1(100,22.96) v1(100.1,24.59) v1(100.05,21.31) v1(100.3,0.71) v1(100.53,35.53) v1(100.61,45.19) v1(100.84,31.06) v1(100.81,27.81) v1(100.89,29.44) v1(100.86,26.21) v1(100.91,19.63) v1(101.27,22.96) v1(101.32,21.31) v1(101.37,24.59) v1(101.52,34.52) v1(101.88,47.64) v1(101.88,45.2) v1(101.88,43.63) v1(102.11,31.06) v1(102.08,27.81) v1(102.13,26.21) v1(102.08,0.71) v1(102.18,46.65) v1(102.16,29.44) v1(102.18,19.63) v1(102.31,35.28) v1(102.34,6.71) v1(102.54,22.96) v1(102.64,24.59) v1(102.59,21.31) v1(102.92,34.52) v1(103.12,9.91) v1(103.23,50.44) v1(103.38,31.06) v1(103.43,29.44) v1(103.35,27.81) v1(103.4,26.21) v1(103.45,19.63) v1(103.5,17.6) v1(103.48,13.03) v1(103.81,22.96) v1(103.76,0.74) v1(103.91,24.59) v1(103.86,21.31) v1(104.65,31.06) v1(104.62,27.81) v1(104.7,29.44) v1(104.67,26.21) v1(104.72,19.63) v1(104.88,0.71) v1(105.08,22.96) v1(105.13,21.31) v1(105.18,24.59) v1(105.54,11.81) v1(105.69,36.27) v1(105.92,31.06) v1(105.89,27.81) v1(105.94,26.21) v1(105.97,29.44) v1(105.99,19.63) v1(106.15,35.28) v1(106.23,49.35) v1(106.35,22.96) v1(106.35,4.32) v1(106.37,43.25) v1(106.4,21.31) v1(106.4,2.79) v1(106.45,24.59) v1(106.68,11.4) v1(106.71,0.66) v1(106.78,36.65) v1(107.01,53.15) v1(107.06,35.74) v1(107.19,31.06) v1(107.24,29.44) v1(107.16,27.81) v1(107.21,26.21) v1(107.26,19.63) v1(107.44,2.84) v1(107.47,4.29) v1(107.62,22.96) v1(107.72,24.59) v1(107.67,21.31) v1(107.77,11.33) v1(107.98,0.66) v1(108.05,42.67) v1(108.13,35.74) v1(108.43,27.81) v1(108.46,31.06) v1(108.51,29.44) v1(108.48,26.21) v1(108.53,19.63) v1(108.46,15.47) v1(108.58,10.79) v1(108.65,52.52) v1(108.89,22.96) v1(108.94,21.31) v1(108.99,24.59) v1(109.07,46.43) v1(109.25,0.66) v1(109.73,31.06) v1(109.7,27.81) v1(109.78,29.44) v1(109.75,26.21) v1(109.8,19.63) v1(110.16,22.96) v1(110.21,21.31) v1(110.26,24.59) v1(110.31,7.72) v1(110.54,15.52) v1(110.52,0.66) v1(110.74,9.25) v1(111,31.06) v1(111.05,29.44) v1(110.97,27.81) v1(111.02,26.21) v1(111.07,19.63) v1(111.43,22.96) v1(111.53,24.59) v1(111.48,21.31) v1(111.63,50.75) v1(111.66,52.3) v1(111.79,0.66) v1(112.09,51.49) v1(112.09,8.26) v1(112.24,27.81) v1(112.27,31.06) v1(112.32,29.44) v1(112.29,26.21) v1(112.34,19.63) v1(112.38,48.83) v1(112.37,47.9) v1(112.37,46.61) v1(112.52,52.3) v1(112.5,50.75) v1(112.7,22.96) v1(112.8,24.59) v1(112.75,21.31) v1(113.06,0.66) v1(113.54,31.06) v1(113.51,27.81) v1(113.59,29.44) v1(113.56,26.21) v1(113.61,19.63) v1(113.97,22.96) v1(114.02,21.31) v1(114.07,24.59) v1(114.27,36.47) v1(114.33,0.66) v1(114.5,33.22) v1(114.58,37.34) v1(114.78,27.81) v1(114.83,26.21) v1(114.91,31.06) v1(114.86,29.44) v1(114.88,19.63) v1(115.09,45.44) v1(115.09,44.63) v1(115.24,22.96) v1(115.34,24.59) v1(115.29,21.31) v1(115.54,50.9) v1(115.62,39.27) v1(115.6,0.66) v1(116.13,29.44) v1(116.05,27.81) v1(116.1,26.21) v1(116.15,19.63) v1(116.51,22.96) v1(116.61,45.44) v1(116.61,44.63) v1(116.61,24.59) v1(116.56,21.31) v1(116.71,50.93) v1(116.76,0.66) v1(117.35,31.06) v1(117.42,19.63) v1(117.63,2.74) v1(117.65,51.16) v1(117.68,17.65) v1(117.78,22.96) v1(117.83,21.31) v1(117.88,24.59) v1(118.03,0.66) v1(118.21,11.3) v1(118.52,45.24) v1(118.59,27.81) v1(118.64,26.21) v1(118.67,29.44) v1(118.69,19.63) v1(118.82,51.13) v1(118.77,2.34) v1(119.05,22.96) v1(119.05,18.11) v1(119.12,41.66) v1(119.1,21.31) v1(119.15,24.59) v1(119.3,0.66) v1(119.35,11.58) v1(119.53,43.64) v1(119.77,41.66) v1(119.94,29.44) v1(119.86,27.81) v1(119.91,26.21) v1(119.89,2.41) v1(119.96,19.63) v1(120.07,42.85) v1(120.14,18.36) v1(120.32,22.96) v1(120.45,31.04) v1(120.42,24.59) v1(120.37,21.31) v1(120.47,13.08) v1(120.57,0.66) v1(120.65,1.91) v1(121.06,41.1) v1(121.13,27.81) v1(121.21,29.44) v1(121.18,26.21) v1(121.23,19.63) v1(121.34,18.75) v1(121.26,12.55) v1(121.64,40.54) v1(121.59,22.96) v1(121.64,21.31) v1(121.69,24.59) v1(121.84,0.66) v1(121.95,31.04) v1(122.12,18.47) v1(122.35,50.83) v1(122.4,27.81) v1(122.5,45.47) v1(122.5,44.65) v1(122.53,32.99) v1(122.48,29.44) v1(122.45,26.21) v1(122.5,19.63) v1(122.58,3.73) v1(122.56,2.18) v1(122.86,22.96) v1(122.91,21.31) v1(122.89,18.14) v1(122.99,39.4) v1(122.96,24.59) v1(123.11,0.66) v1(123.16,37.69) v1(123.44,50.83) v1(123.39,31.06) v1(123.55,45.42) v1(123.55,44.6) v1(123.75,29.44) v1(123.67,27.81) v1(123.72,26.21) v1(123.77,19.63) v1(123.95,18.75) v1(124.13,22.96) v1(124.23,24.59) v1(124.18,21.31) v1(124.38,51.21) v1(124.66,31.06) v1(124.94,27.81) v1(125.02,29.44) v1(124.99,26.21) v1(125.04,19.63) v1(125.32,32.89) v1(125.4,22.96) v1(125.43,18.39) v1(125.5,24.59) v1(125.45,21.31) v1(125.7,51.21) v1(125.93,31.06) v1(126.24,45.09) v1(126.21,27.81) v1(126.26,26.21) v1(126.31,19.63) v1(126.49,41.71) v1(126.72,21.31) v1(126.77,24.59) v1(126.8,18.39) v1(126.92,43.61) v1(127.14,41.71) v1(127.25,29.41) v1(127.43,32.79) v1(127.46,42.82) v1(127.53,26.21) v1(127.58,19.63) v1(127.97,50.72) v1(127.99,21.31) v1(128.22,45.11) v1(128.42,40.97) v1(128.45,12.09) v1(128.63,42.29) v1(128.65,22.96) v1(128.83,29.44) v1(128.75,27.81) v1(128.8,26.21) v1(128.88,40.41) v1(128.85,19.63) v1(129.08,50.7) v1(129.16,35) v1(129.26,21.31) v1(129.41,31.04) v1(129.49,24.59) v1(129.64,32.77) v1(129.92,45.36) v1(129.92,44.55) v1(129.92,22.96) v1(130.02,27.81) v1(130.07,51.08) v1(130.12,19.63) v1(130.43,39.34) v1(130.56,37.67) v1(130.89,29.44) v1(130.91,21.31) v1(130.96,32.77) v1(131.04,26.19) v1(130.96,24.59) v1(131.24,22.96) v1(131.32,31.06) v1(131.39,51.08) v1(131.44,45.36) v1(131.44,44.55) v1(131.39,19.63) v1(132.04,12.83) v1(132.11,26.19) v1(132.23,32.77) v1(132.51,27.84) v1(132.59,31.06) v1(132.64,22.99) v1(132.61,21.36) v1(132.66,24.61) v1(133.05,12.83) v1(133.5,32.77) v1(133.76,31.06) v1(133.95,41.64) v1(134.14,24.56) v1(134.14,22.96) v1(134.21,26.24) v1(134.16,21.34) v1(134.34,29.44) v1(134.37,43.59) v1(134.65,45.31) v1(134.6,41.64) v1(134.57,27.81) v1(134.92,42.8) v1(134.87,32.74) v1(135.08,13.18) v1(135.13,11.33) v1(135.59,29.41) v1(135.66,31.04) v1(135.76,42.01) v1(135.84,27.81) v1(135.92,40.97) v1(135.92,24.59) v1(135.92,22.96) v1(136.12,34.11) v1(136.19,26.21) v1(136.58,47.22) v1(136.6,45.31) v1(136.68,40.41) v1(136.98,29.41) v1(137.08,31.04) v1(137.13,27.81) v1(137.08,21.29) v1(137.36,11.23) v1(137.41,1.04) v1(137.49,32.77) v1(137.46,26.21) v1(137.74,46.05) v1(137.85,48.46) v1(137.82,24.61) v1(137.92,20.5) v1(137.9,2.03) v1(138.13,13.16) v1(138.07,8.74) v1(138.23,59.64) v1(138.25,29.41) v1(138.3,22.61) v1(138.35,31.04) v1(138.4,27.81) v1(138.4,26.19) v1(138.43,15.16) v1(138.71,17.14) v1(138.66,1.04) v1(138.94,49.91) v1(139.01,44.78) v1(138.96,19.46) v1(139.09,47.19) v1(139.34,21.56) v1(139.45,26.24) v1(139.5,32.26) v1(139.6,23.95) v1(139.62,16.28) v1(139.83,31.04) v1(139.8,29.41) v1(139.78,27.79) v1(139.9,18.54) v1(139.95,14.12) v1(139.95,1.04) v1(140.18,20.73) v1(140.26,51.21) v1(140.28,41.53) v1(140.28,37.77) v1(140.28,34.19) v1(140.36,48.49) v1(140.39,45.92) v1(140.44,12.83) v1(140.44,2.03) v1(140.54,43.28) v1(140.51,6.32) v1(140.61,39.32) v1(140.56,35.64) v1(140.61,15.24) v1(140.84,25.15) v1(140.94,27.74) v1(141,53.11) v1(140.97,32.77) v1(141.02,19.91) v1(141.15,50.29) v1(141.1,31.04) v1(141.07,29.41) v1(141.15,17.27) v1(141.25,3.48) v1(141.2,1.04) v1(141.4,42.27) v1(141.58,44.7) v1(141.58,24.49) v1(141.68,47.12) v1(142.06,4.93) v1(142.34,57.91) v1(142.34,52.83) v1(142.34,41.4) v1(142.34,33.78) v1(142.34,18.54) v1(142.34,10.92) v1(142.49,1.04) v1(143.03,26.82) v1(142.98,2.03) v1(143.05,3.56) v1(143.38,63.98) v1(143.61,59.18) v1(143.61,54.1) v1(143.61,42.67) v1(143.61,35.05) v1(143.61,31.24) v1(143.61,19.81) v1(143.61,12.19) v1(143.61,9.65) v1(143.74,1.04) v1(143.97,5.59) v1(144.88,52.83) v1(144.88,18.54) v1(144.88,10.92) v1(145.19,62.43) v1(146.15,59.18) v1(146.15,54.1) v1(146.15,35.05) v1(146.15,23.62) v1(146.15,19.81) v1(146.15,16) v1(146.15,9.65) v1(146.79,7.92) v1(147.42,52.83) v1(147.42,45.21) v1(147.42,37.59) v1(147.42,18.54) v1(147.42,14.73) v1(147.42,10.92) v1(147.8,5.49) v1(148.31,1.02) v1(148.67,64.64) v1(148.69,59.18) v1(148.69,38.86) v1(148.69,19.81) v1(148.69,16) v1(148.69,9.65) v1(148.69,7.11) v1(149.4,3.25) v1(149.56,66.27) v1(149.96,57.91) v1(149.96,52.83) v1(149.96,51.56) v1(149.96,28.7) v1(149.96,13.46) v1(149.96,10.92) v1(149.99,0.99) v1(150.37,7.75) v1(150.83,63.09) v1(151.23,59.18) v1(151.23,55.37) v1(151.23,54.1) v1(151.23,50.29) v1(151.23,49.02) v1(151.23,35.05) v1(151.23,33.78) v1(151.23,29.97) v1(151.23,28.7) v1(151.23,24.89) v1(151.23,23.62) v1(151.23,19.81) v1(151.23,18.54) v1(151.23,14.73) v1(151.23,9.65) v1(152.07,60.93) v1(152.5,57.91) v1(152.5,56.64) v1(152.5,51.56) v1(152.5,37.59) v1(152.5,36.32) v1(152.5,32.51) v1(152.5,31.24) v1(152.5,26.16) v1(152.5,21.08) v1(152.5,16) v1(152.5,10.92) v1(153.14,7.11) v1(153.77,59.18) v1(153.77,55.37) v1(153.77,54.1) v1(153.77,50.29) v1(153.77,49.02) v1(153.77,43.94) v1(153.77,38.86) v1(153.77,35.05) v1(153.77,33.78) v1(153.77,29.97) v1(153.77,24.89) v1(153.77,19.81) v1(153.77,14.73) v1(153.77,9.65) v1(154,66.27) v1(154.08,1.02) v1(154.41,3.94) v1(154.76,5.54) v1(155.37,1.02) v1(155.52,17.37) v1(156.62,1.02) v2(0.61,65.02) v2(0.61,63.88) v2(0.61,62.74) v2(0.61,57.91) v2(0.61,56.77) v2(0.61,55.63) v2(0.61,51.03) v2(0.61,49.89) v2(0.61,48.74) v2(0.61,43.92) v2(0.61,42.77) v2(0.61,41.63) v2(0.61,36.32) v2(0.61,35.18) v2(0.61,34.04) v2(0.61,29.21) v2(0.61,28.07) v2(0.61,26.92) v2(0.61,23.62) v2(0.61,22.48) v2(0.61,21.34) v2(0.61,16.51) v2(0.61,15.37) v2(0.61,14.22) v2(0.61,10.92) v2(0.61,9.78) v2(0.61,8.64) v2(0.61,3.81) v2(0.61,2.67) v2(0.61,1.52) v2(0.89,39.07) v2(1.7,40.06) v2(1.7,38.18) v2(2.13,65.02) v2(2.13,63.88) v2(2.13,62.74) v2(2.13,57.91) v2(2.13,56.77) v2(2.13,55.63) v2(2.13,51.03) v2(2.13,49.89) v2(2.13,48.74) v2(2.13,43.92) v2(2.13,42.77) v2(2.13,41.63) v2(2.13,36.32) v2(2.13,35.18) v2(2.13,34.04) v2(2.13,29.21) v2(2.13,28.07) v2(2.13,26.92) v2(2.13,23.62) v2(2.13,22.48) v2(2.13,21.34) v2(2.13,16.51) v2(2.13,15.37) v2(2.13,14.22) v2(2.13,10.92) v2(2.13,9.78) v2(2.13,8.64) v2(2.13,3.81) v2(2.13,2.67) v2(2.13,1.52) v2(2.41,39.07) v2(3.35,40.06) v2(3.35,38.18) v2(3.66,65.02) v2(3.66,63.88) v2(3.66,62.74) v2(3.66,51.03) v2(3.66,49.89) v2(3.66,48.74) v2(3.66,36.32) v2(3.66,35.18) v2(3.66,34.04) v2(3.66,23.62) v2(3.66,22.48) v2(3.66,21.34) v2(3.66,10.92) v2(3.66,9.78) v2(3.66,8.64) v2(3.78,57.91) v2(3.78,56.77) v2(3.78,55.63) v2(3.78,43.92) v2(3.78,42.77) v2(3.78,41.63) v2(3.78,29.21) v2(3.78,28.07) v2(3.78,26.92) v2(3.78,16.51) v2(3.78,15.37) v2(3.78,14.22) v2(3.78,3.81) v2(3.78,2.67) v2(3.78,1.52) v2(4.06,39.07) v2(5.13,40.06) v2(5.13,38.18) v2(5.84,39.07) v2(6.65,40.06) v2(6.65,38.18) v2(7.37,39.07) v2(8.31,40.06) v2(8.31,38.18) v2(9.02,39.07) v2(10.16,40.08) v2(10.69,39.01) v2(12.27,40.11) v2(14.25,40.08) v2(22.15,45.85) v2(23.7,45.85) v2(26.09,41.58) v2(26.47,42.32) v2(26.57,44.48) v2(32.1,61.18) v2(32.1,59.86) v2(32.1,58.55) v2(32.1,57.36) v2(32.1,56.17) v2(33.41,61.18) v2(33.41,59.86) v2(33.41,58.55) v2(33.41,57.36) v2(33.41,56.17) v2(34.73,61.18) v2(34.73,59.86) v2(34.73,58.55) v2(34.73,57.36) v2(34.73,56.17) v2(36.04,62.49) v2(36.04,61.18) v2(36.04,59.86) v2(36.04,58.55) v2(36.04,57.36) v2(36.04,56.17) v2(36.04,54.6) v2(37.36,62.49) v2(37.36,61.18) v2(37.36,59.86) v2(37.36,58.55) v2(37.36,57.36) v2(37.36,56.17) v2(38.67,62.49) v2(38.67,61.18) v2(38.67,59.86) v2(38.67,58.55) v2(38.67,57.36) v2(38.67,56.17) v2(38.67,54.6) v2(39.99,62.49) v2(39.99,61.18) v2(39.99,59.86) v2(39.99,58.55) v2(39.99,57.36) v2(39.99,56.17) v2(39.99,54.6) v2(109.27,41) v2(109.27,39.98) v2(109.27,38.96) v2(110.29,39.98) v2(110.29,38.96) v2(142.34,49.02) v2(148.69,50.29) v2(148.69,42.67) v3(0.69,67.97) v3(1.96,67.97) v3(3.23,67.97) v3(4.5,67.97) v3(5.77,67.97) v3(8.36,33.66) v3(8.48,31.98) v3(9.27,34.77) v3(9.58,67.97) v3(10.36,35.84) v3(10.85,67.97) v3(11.4,38.96) v3(11.4,36.88) v3(12.12,67.97) v3(12.8,35.59) v3(13.39,67.97) v3(14.2,35.64) v3(14.66,67.97) v3(15.93,67.97) v3(17.2,67.97) v3(18.01,16.03) v3(18.47,67.97) v3(19.74,67.97) v3(21.01,67.97) v3(21.07,20.46) v3(22.05,57.53) v3(21.97,16.15) v3(22.28,67.97) v3(23.55,67.97) v3(24.66,59.97) v3(24.82,67.97) v3(26.09,67.97) v3(27.36,67.97) v3(27.41,60.22) v3(28.22,67.97) v3(29.64,59.72) v3(29.72,66.47) v3(29.67,57.35) v3(29.9,67.97) v3(29.95,55.02) v3(30.2,53.52) v3(31.17,67.97) v3(31.29,66.45) v3(32.28,33.02) v3(32.74,68) v3(32.79,66.45) v3(34.04,32.99) v3(34.19,68) v3(34.24,66.45) v3(34.19,35.94) v3(34.92,32.92) v3(35.18,51.99) v3(35.59,68) v3(35.64,66.45) v3(35.74,64.97) v3(35.79,51.99) v3(36.25,32.92) v3(36.35,64.97) v3(36.4,51.99) v3(36.83,68) v3(36.88,66.45) v3(36.96,64.97) v3(37.03,51.99) v3(37.21,33.45) v3(37.77,50.52) v3(38.18,68) v3(38.23,66.45) v3(38.79,65.02) v3(38.79,52.07) v3(38.99,33.45) v3(39.07,48.95) v3(39.45,68) v3(39.5,66.45) v3(39.7,38.66) v3(39.83,45.13) v3(39.78,33.45) v3(41,68.05) v3(41,66.45) v3(41.22,48.51) v3(41.58,33.43) v3(41.66,51.77) v3(41.76,63.96) v3(41.88,45.21) v3(42.44,68.05) v3(42.44,66.45) v3(42.42,64.64) v3(42.65,51.77) v3(42.7,48.34) v3(43.33,44.48) v3(43.31,34.75) v3(43.54,64.64) v3(43.64,38.43) v3(43.66,48.39) v3(43.84,68.05) v3(43.84,66.45) v3(43.89,46.61) v3(44.4,39.8) v3(44.73,52.04) v3(44.65,48.41) v3(44.73,46.63) v3(44.83,64.67) v3(44.88,45.97) v3(45.09,68.05) v3(45.09,66.45) v3(45.31,52.6) v3(45.29,45.39) v3(45.69,48.36) v3(45.67,46.71) v3(46,52.04) v3(46.08,52.98) v3(46.23,44.98) v3(46.43,68.05) v3(46.43,66.45) v3(46.61,46.69) v3(46.66,48.36) v3(46.81,64.64) v3(46.81,63.02) v3(46.81,61.39) v3(46.81,59.79) v3(46.81,58.14) v3(46.84,56.54) v3(46.81,53.16) v3(47.14,45.39) v3(47.37,49.05) v3(47.5,54.86) v3(47.6,46.96) v3(47.7,68.05) v3(47.7,66.45) v3(47.73,53.16) v3(47.7,51.92) v3(48.08,64.64) v3(48.08,63.02) v3(48.08,61.39) v3(48.08,58.14) v3(48.06,56.52) v3(48.16,59.77) v3(48.34,50.04) v3(48.31,44.42) v3(48.49,47.83) v3(48.59,51.51) v3(49,53.16) v3(49.2,54.86) v3(49.28,68.05) v3(49.25,66.45) v3(49.3,58.14) v3(49.35,64.64) v3(49.35,63.02) v3(49.4,61.39) v3(49.38,59.79) v3(49.38,56.54) v3(49.48,51.23) v3(49.53,48.87) v3(50.29,53.19) v3(50.37,56.52) v3(50.44,52.15) v3(50.52,54.84) v3(50.62,64.64) v3(50.62,63.02) v3(50.62,61.39) v3(50.65,59.79) v3(50.62,58.14) v3(50.72,68.05) v3(50.7,66.45) v3(50.72,50.06) v3(51.31,56.52) v3(51.46,53.16) v3(51.69,51.03) v3(51.82,54.84) v3(51.89,64.64) v3(51.89,63.02) v3(51.89,61.39) v3(51.92,59.79) v3(51.89,58.14) v3(52.12,68.05) v3(52.1,66.45) v3(52.35,56.52) v3(52.76,59.79) v3(52.81,58.14) v3(52.78,52.12) v3(53.06,61.39) v3(53.16,64.64) v3(53.16,63.02) v3(53.16,54.86) v3(53.34,66.45) v3(53.37,68.05) v3(53.52,56.52) v3(53.7,59.79) v3(53.77,58.14) v3(53.8,53.16) v3(54.43,64.64) v3(54.43,63.02) v3(54.43,61.39) v3(54.48,54.84) v3(54.58,58.17) v3(54.71,68.05) v3(54.69,66.45) v3(54.71,59.77) v3(54.69,56.54) v3(55.24,53.19) v3(55.4,64.64) v3(55.4,58.14) v3(55.7,63.02) v3(55.7,61.39) v3(55.73,59.79) v3(55.73,56.54) v3(55.98,68.05) v3(55.96,66.45) v3(55.98,54.84) v3(56.41,58.17) v3(56.52,53.19) v3(56.57,56.52) v3(56.85,64.64) v3(56.97,63.02) v3(56.97,61.39) v3(57,59.79) v3(56.97,54.84) v3(57.28,68) v3(57.35,66.45) v3(57.4,58.14) v3(57.56,56.54) v3(57.91,54.84) v3(57.86,53.16) v3(58.24,63.02) v3(58.24,61.39) v3(58.24,58.14) v3(58.27,59.79) v3(58.55,56.54) v3(58.83,68.02) v3(58.8,66.37) v3(58.9,54.84) v3(59.11,52.78) v3(59.28,64.69) v3(59.51,61.39) v3(59.54,59.79) v3(59.51,58.14) v3(59.54,56.54) v3(59.87,54.84) v3(60.05,66.34) v3(60.25,67.97) v3(60.35,53.16) v3(60.5,64.67) v3(60.81,59.79) v3(60.78,58.14) v3(60.81,56.54) v3(60.78,54.84) v3(60.93,63.04) v3(61.24,66.29) v3(61.52,67.97) v3(61.59,64.67) v3(61.85,59.77) v3(62.05,58.14) v3(62.08,56.54) v3(62.05,54.84) v3(62.15,63.02) v3(62.2,51.18) v3(62.26,50.22) v3(62.53,61.39) v3(62.79,67.97) v3(62.76,66.29) v3(62.81,64.69) v3(63.32,63.04) v3(63.32,58.14) v3(63.35,56.54) v3(63.32,54.84) v3(63.5,52.53) v3(63.63,49.43) v3(63.83,61.37) v3(64.03,66.29) v3(64.03,64.64) v3(64.06,67.97) v3(64.19,59.77) v3(64.29,48.74) v3(64.36,53.16) v3(64.49,63.04) v3(64.62,56.54) v3(64.59,54.84) v3(64.8,51.05) v3(65.02,61.39) v3(65.33,67.97) v3(65.3,66.29) v3(65.3,64.64) v3(65.33,47.42) v3(65.41,59.77) v3(65.68,53.16) v3(65.76,63.04) v3(65.79,58.14) v3(65.86,54.84) v3(65.96,46.91) v3(65.96,46.43) v3(66.12,61.39) v3(66.6,67.97) v3(66.57,66.29) v3(66.57,64.64) v3(66.62,59.77) v3(66.62,46.91) v3(66.62,46.43) v3(66.88,53.14) v3(67.03,63.04) v3(67.01,58.14) v3(67.08,49.78) v3(67.08,43.71) v3(67.21,47.42) v3(67.21,45.54) v3(67.39,61.39) v3(67.44,56.52) v3(67.74,59.79) v3(67.84,66.29) v3(67.84,64.64) v3(67.87,67.97) v3(68.1,58.17) v3(68.3,63.04) v3(68.55,45.59) v3(68.66,61.39) v3(68.66,56.52) v3(68.71,54.86) v3(68.81,51.89) v3(68.88,53.11) v3(69.01,59.79) v3(69.14,67.97) v3(69.11,66.29) v3(69.11,64.64) v3(69.06,50.7) v3(69.06,49.78) v3(69.06,44.98) v3(69.06,44.32) v3(69.34,58.17) v3(69.52,51.66) v3(69.57,63.04) v3(69.85,56.52) v3(69.93,61.39) v3(69.98,54.86) v3(70.13,51.66) v3(70.05,44.98) v3(70.05,44.3) v3(70.15,53.11) v3(70.28,59.79) v3(70.41,67.97) v3(70.38,66.29) v3(70.38,64.64) v3(70.61,58.17) v3(70.84,63.04) v3(70.99,56.52) v3(71.04,44.98) v3(71.04,44.3) v3(71.2,61.39) v3(71.25,54.86) v3(71.42,53.11) v3(71.4,46.91) v3(71.4,46.3) v3(71.55,59.79) v3(71.68,67.97) v3(71.65,66.29) v3(71.65,64.64) v3(71.88,58.17) v3(71.98,45.42) v3(72.11,63.04) v3(72.26,56.52) v3(72.47,61.39) v3(72.52,54.86) v3(72.69,53.11) v3(72.67,45.92) v3(72.69,45.42) v3(72.82,59.79) v3(72.95,67.97) v3(72.92,66.29) v3(72.92,64.64) v3(73.15,58.17) v3(73.28,46.91) v3(73.38,63.04) v3(73.38,51.36) v3(73.53,56.52) v3(73.74,61.39) v3(73.79,54.86) v3(73.96,53.11) v3(74.09,59.79) v3(74.22,67.97) v3(74.19,66.29) v3(74.19,64.64) v3(74.42,58.17) v3(74.4,47.93) v3(74.65,63.04) v3(74.8,56.52) v3(75.01,61.39) v3(75.03,47.93) v3(75.06,54.86) v3(75.23,53.11) v3(75.36,59.79) v3(75.49,67.97) v3(75.46,66.29) v3(75.46,64.64) v3(75.69,58.17) v3(75.74,51.31) v3(75.92,63.04) v3(76.07,56.52) v3(76.28,61.39) v3(76.33,54.86) v3(76.5,53.11) v3(76.63,59.79) v3(76.73,66.29) v3(76.73,64.64) v3(76.76,67.97) v3(76.89,47.93) v3(76.96,58.17) v3(77.19,63.04) v3(77.34,56.52) v3(77.55,61.39) v3(77.6,54.86) v3(77.77,53.11) v3(77.9,59.79) v3(78.03,67.97) v3(78,66.29) v3(78,64.64) v3(78.23,58.17) v3(78.46,63.04) v3(78.61,56.52) v3(78.82,61.39) v3(78.87,54.86) v3(79.04,53.11) v3(79.17,59.79) v3(79.3,67.97) v3(79.27,66.29) v3(79.27,64.64) v3(79.5,58.17) v3(79.73,63.04) v3(79.88,56.52) v3(80.09,61.39) v3(80.14,54.86) v3(80.31,53.11) v3(80.44,59.79) v3(80.54,66.29) v3(80.54,64.64) v3(80.57,67.97) v3(80.77,58.17) v3(81,63.04) v3(81.15,56.52) v3(81.36,61.39) v3(81.41,54.86) v3(81.58,53.11) v3(81.71,59.79) v3(81.84,67.97) v3(81.81,66.29) v3(81.81,64.64) v3(82.04,58.17) v3(82.27,63.04) v3(82.42,56.52) v3(82.63,61.39) v3(82.68,54.86) v3(82.85,53.11) v3(82.98,59.79) v3(83.11,67.97) v3(83.08,66.29) v3(83.08,64.64) v3(83.31,58.17) v3(83.54,63.04) v3(83.69,56.52) v3(83.9,61.39) v3(83.95,54.86) v3(84.12,53.11) v3(84.25,59.79) v3(84.38,67.97) v3(84.35,66.29) v3(84.35,64.64) v3(84.58,58.17) v3(84.81,63.04) v3(84.96,56.52) v3(85.17,61.39) v3(85.22,54.86) v3(85.39,53.11) v3(85.52,59.79) v3(85.65,67.97) v3(85.62,66.29) v3(85.62,64.64) v3(85.78,51.92) v3(85.85,58.17) v3(86.08,63.04) v3(86.23,56.52) v3(86.44,61.39) v3(86.49,54.86) v3(86.66,53.11) v3(86.79,59.79) v3(86.92,67.97) v3(87.12,58.17) v3(87.35,63.04) v3(87.5,56.52) v3(87.63,34.98) v3(87.63,34.49) v3(87.71,61.39) v3(87.76,54.86) v3(87.93,53.11) v3(88.06,59.79) v3(88.11,47.22) v3(88.09,45.75) v3(88.11,45.31) v3(88.19,67.97) v3(88.16,66.29) v3(88.16,64.64) v3(88.39,58.17) v3(88.62,63.04) v3(88.77,56.52) v3(88.98,61.39) v3(89.03,54.86) v3(89.03,51.92) v3(89.2,53.11) v3(89.33,59.79) v3(89.43,66.29) v3(89.43,64.64) v3(89.46,67.97) v3(89.66,58.17) v3(89.89,63.04) v3(90.04,56.52) v3(90.25,61.39) v3(90.3,54.86) v3(90.47,53.11) v3(90.6,59.79) v3(90.73,67.97) v3(90.7,66.29) v3(90.7,64.64) v3(90.93,58.17) v3(91.16,63.04) v3(91.31,56.52) v3(91.52,61.39) v3(91.54,48.65) v3(91.57,54.86) v3(91.74,53.11) v3(91.87,59.79) v3(92,67.97) v3(91.97,66.29) v3(91.97,64.64) v3(92.2,58.17) v3(92.43,63.04) v3(92.39,48.65) v3(92.58,56.52) v3(92.79,61.39) v3(92.84,54.86) v3(93.01,53.11) v3(93.14,59.79) v3(93.24,66.29) v3(93.24,64.64) v3(93.22,48.65) v3(93.27,67.97) v3(93.47,58.17) v3(93.7,63.04) v3(93.85,56.52) v3(94.06,61.39) v3(94.11,54.86) v3(94.28,53.11) v3(94.41,59.79) v3(94.54,67.97) v3(94.51,66.29) v3(94.51,64.64) v3(94.74,58.17) v3(94.97,63.04) v3(95.12,56.52) v3(95.33,61.39) v3(95.27,51.06) v3(95.27,50.19) v3(95.38,54.86) v3(95.55,53.11) v3(95.68,59.79) v3(95.81,67.97) v3(95.78,66.29) v3(95.78,64.64) v3(96.01,58.17) v3(96.24,63.04) v3(96.39,56.52) v3(96.6,61.39) v3(96.65,54.86) v3(96.82,53.11) v3(96.95,59.79) v3(97.08,67.97) v3(97.05,66.29) v3(97.05,64.64) v3(97.28,58.17) v3(97.51,63.04) v3(97.66,56.52) v3(97.77,40.24) v3(97.77,39.4) v3(97.87,61.39) v3(97.92,54.86) v3(98.09,53.11) v3(98.22,59.79) v3(98.35,67.97) v3(98.32,66.29) v3(98.32,64.64) v3(98.55,58.17) v3(98.78,63.04) v3(98.93,56.52) v3(99.14,61.39) v3(99.19,54.86) v3(99.21,53.14) v3(99.49,59.79) v3(99.62,67.97) v3(99.59,66.29) v3(99.59,64.64) v3(99.82,58.17) v3(100.05,63.04) v3(100.2,56.52) v3(100.41,61.39) v3(100.46,54.86) v3(100.48,53.14) v3(100.76,59.79) v3(100.89,67.97) v3(100.86,66.29) v3(100.86,64.64) v3(101.09,58.17) v3(101.32,63.04) v3(101.47,56.52) v3(101.68,61.39) v3(101.73,54.86) v3(101.75,53.14) v3(102.03,59.79) v3(102.13,66.29) v3(102.13,64.64) v3(102.16,67.97) v3(102.36,58.17) v3(102.59,63.04) v3(102.74,56.52) v3(102.95,61.39) v3(103,54.86) v3(103.02,53.14) v3(103.3,59.79) v3(103.43,67.97) v3(103.4,66.29) v3(103.4,64.64) v3(103.45,43.15) v3(103.63,58.17) v3(103.61,47.14) v3(103.58,44.59) v3(103.86,63.04) v3(103.91,43.15) v3(104.01,56.52) v3(104.02,49.16) v3(104.22,61.39) v3(104.27,54.86) v3(104.44,53.11) v3(104.57,59.79) v3(104.7,67.97) v3(104.67,66.29) v3(104.67,64.64) v3(104.9,58.17) v3(105.13,63.04) v3(105.28,56.52) v3(105.49,61.39) v3(105.54,54.86) v3(105.71,53.11) v3(105.84,59.79) v3(105.94,66.29) v3(105.94,64.64) v3(105.97,67.97) v3(106.17,58.17) v3(106.4,63.04) v3(106.55,56.52) v3(106.76,61.39) v3(106.81,54.86) v3(106.98,53.11) v3(107.11,59.79) v3(107.24,67.97) v3(107.21,66.29) v3(107.21,64.64) v3(107.44,58.17) v3(107.67,63.04) v3(107.82,56.52) v3(108.03,61.39) v3(108.08,54.86) v3(108.25,53.11) v3(108.38,59.79) v3(108.51,67.97) v3(108.48,66.29) v3(108.48,64.64) v3(108.71,58.17) v3(108.94,63.04) v3(109.09,56.52) v3(109.3,61.39) v3(109.35,54.86) v3(109.52,53.11) v3(109.63,42.7) v3(109.63,42.06) v3(109.65,59.79) v3(109.78,67.97) v3(109.75,66.29) v3(109.75,64.64) v3(109.98,58.17) v3(110.21,63.04) v3(110.29,42.7) v3(110.26,42.04) v3(110.36,56.52) v3(110.57,61.39) v3(110.62,54.86) v3(110.79,53.11) v3(110.92,59.79) v3(111.05,67.97) v3(111.02,66.29) v3(111.02,64.64) v3(111.25,58.17) v3(111.48,63.04) v3(111.63,56.52) v3(111.84,61.39) v3(111.89,54.86) v3(112.06,53.11) v3(112.19,59.79) v3(112.32,67.97) v3(112.29,66.29) v3(112.29,64.64) v3(112.52,58.17) v3(112.75,63.04) v3(112.9,56.52) v3(113.11,61.39) v3(113.16,54.86) v3(113.33,53.11) v3(113.46,59.79) v3(113.59,67.97) v3(113.56,66.29) v3(113.56,64.64) v3(113.79,58.17) v3(114.02,63.04) v3(114.17,56.52) v3(114.38,61.39) v3(114.43,54.86) v3(114.6,53.11) v3(114.73,59.79) v3(114.83,66.29) v3(114.83,64.64) v3(114.86,67.97) v3(115.06,58.17) v3(115.29,63.04) v3(115.44,56.52) v3(115.65,61.39) v3(115.7,54.86) v3(115.87,53.11) v3(116,59.79) v3(116.13,67.97) v3(116.1,66.29) v3(116.1,64.64) v3(116.33,58.17) v3(116.56,63.04) v3(116.71,56.52) v3(116.92,61.39) v3(116.97,54.86) v3(117.14,53.11) v3(117.27,59.79) v3(117.4,67.97) v3(117.37,66.29) v3(117.37,64.64) v3(117.6,58.17) v3(117.83,63.04) v3(117.98,56.52) v3(118.19,61.39) v3(118.24,54.86) v3(118.41,53.11) v3(118.54,59.79) v3(118.64,66.29) v3(118.64,64.64) v3(118.67,67.97) v3(118.87,58.17) v3(119.1,63.04) v3(119.25,56.52) v3(119.46,61.39) v3(119.51,54.86) v3(119.68,53.11) v3(119.81,59.79) v3(119.94,67.97) v3(119.91,66.29) v3(119.91,64.64) v3(120.14,58.17) v3(120.37,63.04) v3(120.52,56.52) v3(120.73,61.39) v3(120.78,54.86) v3(120.95,53.11) v3(121.08,59.79) v3(121.21,67.97) v3(121.18,66.29) v3(121.18,64.64) v3(121.41,58.17) v3(121.64,63.04) v3(121.79,56.52) v3(122,61.39) v3(122.05,54.86) v3(122.22,53.11) v3(122.35,59.79) v3(122.48,67.97) v3(122.45,66.29) v3(122.45,64.64) v3(122.68,58.17) v3(122.91,63.04) v3(123.06,56.52) v3(123.27,61.39) v3(123.32,54.86) v3(123.49,53.11) v3(123.62,59.79) v3(123.75,67.97) v3(123.72,66.29) v3(123.72,64.64) v3(123.95,58.17) v3(124.18,63.04) v3(124.33,56.52) v3(124.54,61.39) v3(124.59,54.86) v3(124.76,53.11) v3(124.89,59.79) v3(125.02,67.97) v3(124.99,66.29) v3(124.99,64.64) v3(125.22,58.17) v3(125.45,63.04) v3(125.6,56.52) v3(125.81,61.39) v3(125.86,54.86) v3(126.03,53.11) v3(126.16,59.79) v3(126.29,67.97) v3(126.26,66.29) v3(126.26,64.64) v3(126.49,58.17) v3(126.72,63.04) v3(126.87,56.52) v3(127.08,61.39) v3(127.13,54.86) v3(127.05,51.97) v3(127.43,59.79) v3(127.53,66.29) v3(127.53,64.64) v3(127.56,67.97) v3(127.76,58.17) v3(127.79,54.86) v3(127.99,63.04) v3(128.14,56.52) v3(128.35,61.39) v3(128.57,53.11) v3(128.7,59.79) v3(128.83,67.97) v3(128.8,66.29) v3(128.8,64.64) v3(129.03,58.17) v3(129.06,54.86) v3(129.26,63.04) v3(129.41,56.52) v3(129.54,52.02) v3(129.62,61.39) v3(129.97,59.79) v3(130.1,67.97) v3(130.07,66.29) v3(130.07,64.64) v3(130.23,54.81) v3(130.3,58.17) v3(130.53,63.04) v3(130.68,56.52) v3(130.71,53.11) v3(130.89,61.39) v3(131.24,59.79) v3(131.34,66.29) v3(131.34,64.64) v3(131.34,54.89) v3(131.37,67.97) v3(131.52,52.35) v3(131.57,58.17) v3(131.8,63.04) v3(131.95,56.52) v3(132.16,61.39) v3(132.33,51.56) v3(132.51,59.79) v3(132.64,67.97) v3(132.61,66.29) v3(132.61,64.64) v3(132.84,58.17) v3(133.07,63.04) v3(133.2,53.09) v3(133.17,50.75) v3(133.43,61.39) v3(133.78,59.79) v3(133.76,54.94) v3(133.91,67.97) v3(133.88,66.29) v3(133.88,64.64) v3(134.34,63.04) v3(134.32,51.99) v3(134.7,61.39) v3(134.77,59.21) v3(134.9,56.62) v3(134.87,48.34) v3(135.05,59.79) v3(135.08,53.77) v3(135.13,51.16) v3(135.18,67.97) v3(135.15,66.29) v3(135.15,64.64) v3(135.43,58.55) v3(135.61,63.04) v3(135.84,53.01) v3(135.97,61.39) v3(135.99,59.28) v3(136.42,66.29) v3(136.42,64.64) v3(136.53,67.92) v3(136.53,54.84) v3(136.65,61.39) v3(136.88,63.04) v3(137.49,51.36) v3(137.64,62.84) v3(137.69,66.29) v3(137.69,64.64) v3(137.67,53.8) v3(137.79,67.92) v3(138.18,55.83) v3(138.3,56.52) v3(138.79,58.85) v3(138.94,66.27) v3(138.86,63.93) v3(138.91,61.37) v3(139.06,67.92) v3(139.45,55.83) v3(139.52,58.19) v3(139.78,65.46) v3(139.85,62.97) v3(140.08,60.27) v3(140.34,67.92) v3(140.26,53.7) v3(140.28,11.15) v3(140.46,64.77) v3(141.2,66.22) v3(141.22,59) v3(141.2,56.41) v3(141.27,63.96) v3(141.45,61.39) v3(141.6,67.92) v3(141.73,58.17) v3(141.81,53.44) v3(142.19,63.04) v3(142.49,60.3) v3(142.88,67.92) v3(142.98,54.76) v3(143.1,66.22) v3(143.76,61.47) v3(144.15,67.92) v3(144.32,50.72) v3(146.3,63.42) v3(148.13,67.89) v3(149.4,67.89) v3(149.86,61.54) v3(150.67,67.89) v3(151.51,5.54) v3(151.94,67.89) v3(152.37,64.69) v3(153.21,67.89) v3(153.62,62.53) v3(153.92,64.59) v3(154.48,67.89) v3(155.24,62.56) v3(155.5,20.98) v3(155.75,67.89) v3(156.74,25.96) v3(156.77,67.89) v3(156.77,66.62) v3(156.77,65.35) v3(156.77,64.08) v3(156.77,62.81) v3(156.77,61.54) v3(156.77,60.27) v3(156.77,59) v3(156.77,57.73) v3(156.77,56.46) v3(156.77,55.19) v3(156.77,53.92) v3(156.77,52.65) v3(156.77,51.38) v3(156.77,50.11) v3(156.77,48.84) v3(156.77,46.3) v3(156.77,45.03) v3(156.77,43.76) v3(156.77,42.49) v3(156.77,41.22) v3(156.77,39.95) v3(156.77,38.68) v3(156.77,36.14) v3(156.77,34.87) v3(156.77,33.6) v3(156.77,32.33) v3(156.77,31.06) v3(156.77,29.79) v3(156.77,28.52) v3(156.77,27.25) v3(156.77,24.71) v3(156.77,23.44) v3(156.77,22.17) v3(156.77,20.9) v3(156.77,19.63) v3(156.77,18.36) v3(156.77,17.09) v3(156.77,15.82) v3(156.77,14.55) v3(156.77,13.28) v3(156.77,12.01) v3(156.77,10.74) v3(156.77,9.47) v3(156.77,8.2) v3(156.77,6.93) v3(156.77,5.66) v3(156.77,4.39) v3(156.77,3.12) v3(156.77,1.85) v5(33.17,44.56) v5(33.17,41) v5(33.17,40.11) v5(33.17,38.08) v5(34.18,43.54) v5(34.18,42.65) v5(34.18,41) v5(34.18,40.11) v5(34.18,39.1) v5(34.18,38.08) v5(35.2,43.54) v5(35.2,42.65) v5(35.2,41) v5(35.2,40.11) v5(35.2,39.1) v5(35.2,38.08) v5(36.21,43.54) v5(36.21,42.65) v5(36.21,41) v5(36.21,40.11) v5(36.21,39.1) v5(36.21,38.08) v5(37.23,43.54) v5(37.23,42.65) v5(37.23,41) v5(37.23,40.11) v5(37.23,39.1) v5(37.23,38.08) v5(38.25,43.54) v5(38.25,42.65) v5(38.25,41) v5(38.25,40.11) v5(38.25,39.1) v5(39.26,44.56) v5(39.26,42.65) v5(39.26,40.11) v5(39.26,39.1) v5(64.82,9.27) v5(64.82,8.57) v5(64.82,7.87) v5(65.52,9.27) v5(66.22,9.27) v5(66.22,8.57) v5(66.22,7.87) v5(67.79,49.2) v5(67.79,48.19) v5(67.79,47.17) v5(67.79,46.15) v5(68.8,49.2) v5(68.8,48.18) v5(68.8,47.17) v5(68.8,46.15) v5(69.82,48.18) v5(69.82,47.17) v5(69.82,46.15) v5(70.83,46.15) v6(43.29,4.04) v6(43.29,3.62) v6(43.73,4.04) v6(43.73,3.63) v6(44.16,4.04) v6(44.6,4.04) v6(44.6,3.63) v6(89.28,10.1) v6(89.28,9.35) v6(89.99,10.1) v6(89.99,9.35) v6(89.99,8.6) v6(93.34,15.67) v6(94.03,15.67) v6(94.06,16.42) v6(113.17,10.72) v6(113.17,10.08) v6(113.92,10.72) v6(118.05,40.92) v6(118.05,40.23) v6(118.8,40.92) v6(118.8,40.23) v6(119.55,40.92) v6(119.55,40.23) v6(125.41,40.97) v6(125.41,40.31) v6(126.16,40.97) v6(126.16,40.31) v6(126.91,40.97) v6(126.91,40.31) v6(132.88,40.87) v6(132.88,40.21) v6(133.63,40.87) v6(133.63,40.21) v6(134.38,40.87) v6(134.38,40.21) v7(6.64,53.68) v7(6.78,52.26) v7(8.12,55.3) v7(8.19,50.85) v7(9.18,55.94) v7(9.61,50.71) v7(11.23,52.19) v7(11.87,53.25) v7(14.15,56.87) v7(15.27,56.87) v7(27,41.3) v8(26.95,51.92) v8(28.83,49.53) v8(30.25,50.55) v8(136.58,57.45) v8(138.96,55.19) v8(140.74,54.05)
